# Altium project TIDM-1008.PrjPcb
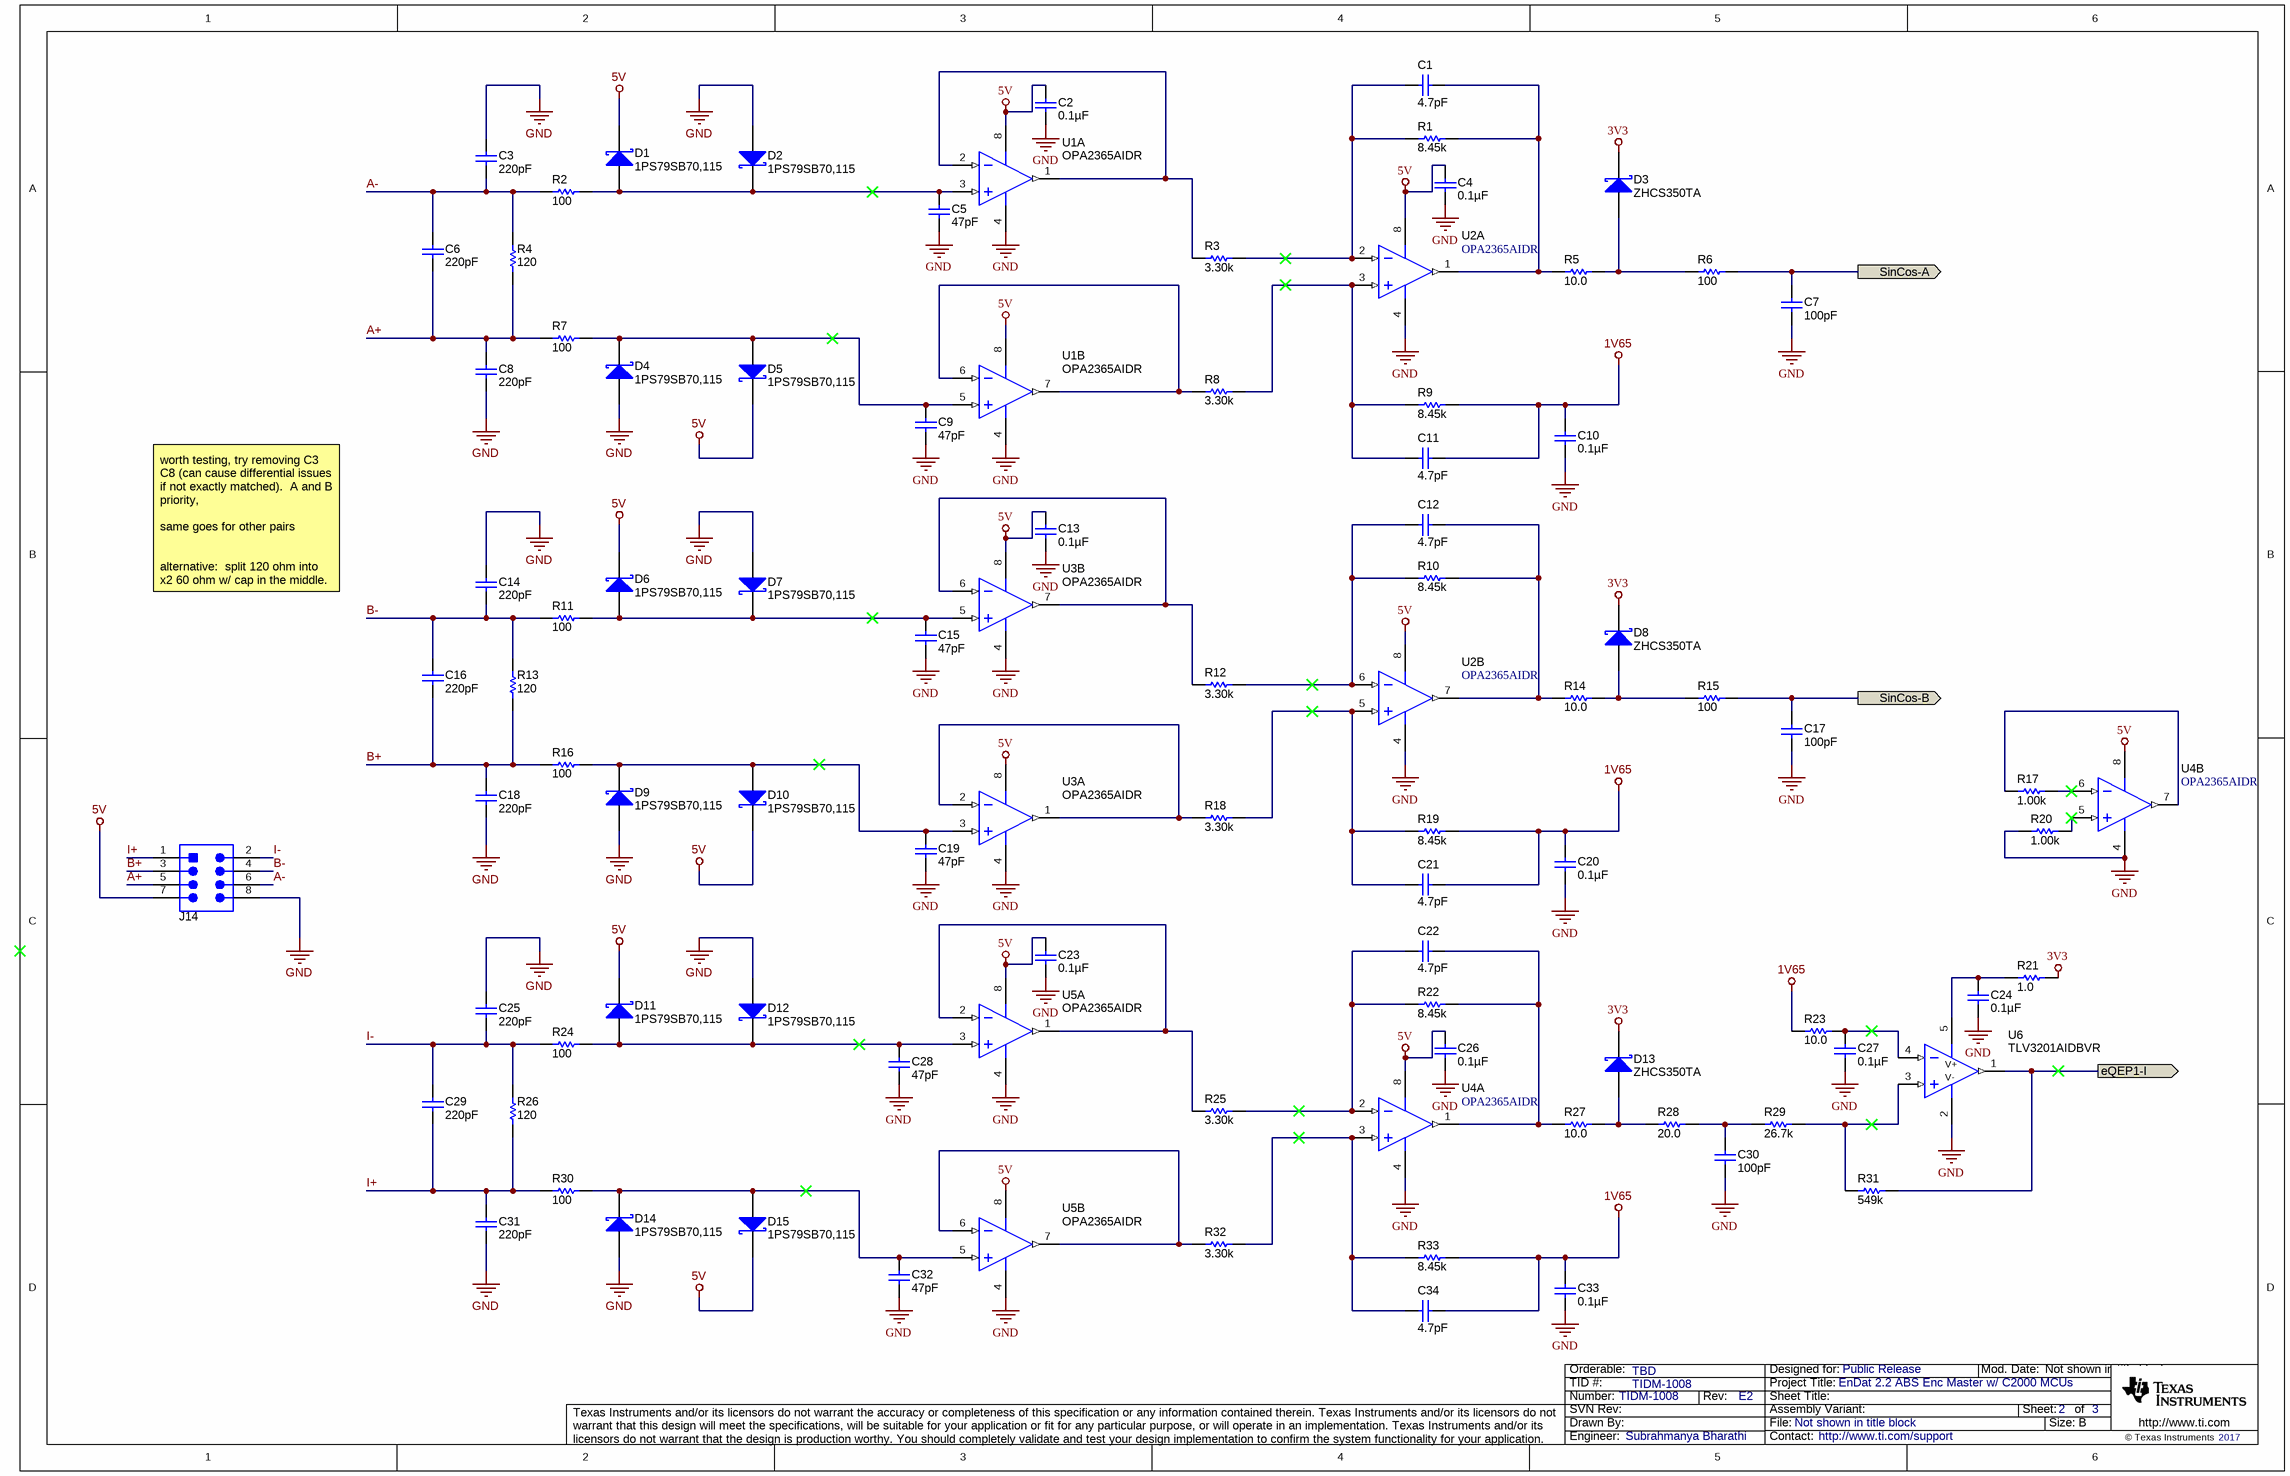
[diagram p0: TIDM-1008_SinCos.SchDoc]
CopyrightYear: 2017; EVM_Orderable: TBD; PCB_Layout: William Stevers; PCB_Rev: 002; PRJ_Customer: Public Release; PRJ_Engineer: Subrahmanya Bharathi; PRJ_Number: TIDM-1008; PRJ_Title: EnDat 2.2 ABS Enc Master w/ C2000 MCUs; SCH_Rev: E2; TechSupport: http://www.ti.com/support; TID: TIDM-1008
5 sheets, 197 parts. Net scope: flat (ports and power ports of the same name join across sheets).
Board file: TIDM-1008_PCB.~(15).PcbDoc
Sheets:
  TIDM-1008_SinCos.SchDoc
  TIDM-1008_AbsEnc.SchDoc
  TIDM-1008_Hardware.SchDoc
  TIDM-1008_Resolver.SchDoc
  TIDM-1008_PowerAndInterface.SchDoc

## Sheet TIDM-1008_SinCos.SchDoc
size 431 x 279 mm; Date: Not shown in title block; ApprovedBy: Not shown in title block; CheckedBy: Not shown in title block; Author: Not shown in title block; CompanyName: Not shown in title block; Engineer: Not shown in title block; Organization: Not shown in title block; Address1: Not shown in title block; Address2: Not shown in title block; Address3: Not shown in title block; Address4: Not shown in title block; DocumentNumber: 1; Revision: Use project parameter SCH_Rev; SheetNumber: 2; SheetTotal: 3; PageSetup: Record=PageOptions¦CenterHorizontal=True¦CenterVertical=True¦PrintScale=1.00¦XCorrection=1.00¦YCorrection=1.00¦PrintKind=0¦BorderSize=5000000¦LeftOffset=0¦BottomOffset=0¦Orientation=2¦PaperLength=1000¦PaperWidth=1000¦Scale=100¦PaperSource=15¦PrintQuality=600¦MediaType=1¦DitherType=10¦PaperKind=Letter¦PrintScaleMode=1

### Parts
C1  ValueDisplayed: 4.7pF  [0402]  (hidden comment: GRM1555C1H4R7WA01D)
C2  ValueDisplayed: 0.1µF  [0603]  (hidden comment: GRM188R71C104KA01D)
C3  ValueDisplayed: 220pF  [0603]  (hidden comment: GRM188R71H221KA01D)
C4  ValueDisplayed: 0.1µF  [0603]  (hidden comment: GRM188R71C104KA01D)
C5  ValueDisplayed: 47pF  [0402]  (hidden comment: GRM1555C1E470JA01D)
C6  ValueDisplayed: 220pF  [0603]  (hidden comment: GRM188R71H221KA01D)
C7  ValueDisplayed: 100pF  [0603]  (hidden comment: GRM1885C2A101JA01D)
C8  ValueDisplayed: 220pF  [0603]  (hidden comment: GRM188R71H221KA01D)
C9  ValueDisplayed: 47pF  [0402]  (hidden comment: GRM1555C1E470JA01D)
C10  ValueDisplayed: 0.1µF  [0402]  (hidden comment: GRM155R71C104KA88D)
C11  ValueDisplayed: 4.7pF  [0402]  (hidden comment: GRM1555C1H4R7WA01D)
C12  ValueDisplayed: 4.7pF  [0402]  (hidden comment: GRM1555C1H4R7WA01D)
C13  ValueDisplayed: 0.1µF  [0603]  (hidden comment: GRM188R71C104KA01D)
C14  ValueDisplayed: 220pF  [0603]  (hidden comment: GRM188R71H221KA01D)
C15  ValueDisplayed: 47pF  [0402]  (hidden comment: GRM1555C1E470JA01D)
C16  ValueDisplayed: 220pF  [0603]  (hidden comment: GRM188R71H221KA01D)
C17  ValueDisplayed: 100pF  [0603]  (hidden comment: GRM1885C2A101JA01D)
C18  ValueDisplayed: 220pF  [0603]  (hidden comment: GRM188R71H221KA01D)
C19  ValueDisplayed: 47pF  [0402]  (hidden comment: GRM1555C1E470JA01D)
C20  ValueDisplayed: 0.1µF  [0402]  (hidden comment: GRM155R71C104KA88D)
C21  ValueDisplayed: 4.7pF  [0402]  (hidden comment: GRM1555C1H4R7WA01D)
C22  ValueDisplayed: 4.7pF  [0402]  (hidden comment: GRM1555C1H4R7WA01D)
C23  ValueDisplayed: 0.1µF  [0603]  (hidden comment: GRM188R71C104KA01D)
C24  ValueDisplayed: 0.1µF  [0603]  (hidden comment: GRM188R71C104KA01D)
C25  ValueDisplayed: 220pF  [0603]  (hidden comment: GRM188R71H221KA01D)
C26  ValueDisplayed: 0.1µF  [0603]  (hidden comment: GRM188R71C104KA01D)
C27  ValueDisplayed: 0.1µF  [0402]  (hidden comment: GRM155R71C104KA88D)
C28  ValueDisplayed: 47pF  [0402]  (hidden comment: GRM1555C1E470JA01D)
C29  ValueDisplayed: 220pF  [0603]  (hidden comment: GRM188R71H221KA01D)
C30  ValueDisplayed: 100pF  [0603]  (hidden comment: GRM1885C2A101JA01D)
C31  ValueDisplayed: 220pF  [0603]  (hidden comment: GRM188R71H221KA01D)
C32  ValueDisplayed: 47pF  [0402]  (hidden comment: GRM1555C1E470JA01D)
C33  ValueDisplayed: 0.1µF  [0402]  (hidden comment: GRM155R71C104KA88D)
C34  ValueDisplayed: 4.7pF  [0402]  (hidden comment: GRM1555C1H4R7WA01D)
D1  1PS79SB70,115  [SOD-523]
D2  1PS79SB70,115  [SOD-523]
D3  ZHCS350TA  [SOD-523]
D4  1PS79SB70,115  [SOD-523]
D5  1PS79SB70,115  [SOD-523]
D6  1PS79SB70,115  [SOD-523]
D7  1PS79SB70,115  [SOD-523]
D8  ZHCS350TA  [SOD-523]
D9  1PS79SB70,115  [SOD-523]
D10  1PS79SB70,115  [SOD-523]
D11  1PS79SB70,115  [SOD-523]
D12  1PS79SB70,115  [SOD-523]
D13  ZHCS350TA  [SOD-523]
D14  1PS79SB70,115  [SOD-523]
D15  1PS79SB70,115  [SOD-523]
J14  70246-0801  [Molex_70246-0801]  (value not drawn)
R1  ValueDisplayed: 8.45k  [0402]  (hidden comment: ERA-2AEB8451X)
R2  ValueDisplayed: 100  [0402]  (hidden comment: CRCW0402100RJNED)
R3  ValueDisplayed: 3.30k  [0402]  (hidden comment: ERJ-2RKF3301X)
R4  ValueDisplayed: 120  [0603]  (hidden comment: CRCW0603120RJNEA)
R5  ValueDisplayed: 10.0  [0402]  (hidden comment: CRCW040210R0FKED)
R6  ValueDisplayed: 100  [0402]  (hidden comment: CRCW0402100RJNED)
R7  ValueDisplayed: 100  [0402]  (hidden comment: CRCW0402100RJNED)
R8  ValueDisplayed: 3.30k  [0402]  (hidden comment: ERJ-2RKF3301X)
R9  ValueDisplayed: 8.45k  [0402]  (hidden comment: ERA-2AEB8451X)
R10  ValueDisplayed: 8.45k  [0402]  (hidden comment: ERA-2AEB8451X)
R11  ValueDisplayed: 100  [0402]  (hidden comment: CRCW0402100RJNED)
R12  ValueDisplayed: 3.30k  [0402]  (hidden comment: ERJ-2RKF3301X)
R13  ValueDisplayed: 120  [0603]  (hidden comment: CRCW0603120RJNEA)
R14  ValueDisplayed: 10.0  [0402]  (hidden comment: CRCW040210R0FKED)
R15  ValueDisplayed: 100  [0402]  (hidden comment: CRCW0402100RJNED)
R16  ValueDisplayed: 100  [0402]  (hidden comment: CRCW0402100RJNED)
R17  ValueDisplayed: 1.00k  [0402]  (hidden comment: CRCW04021K00FKED)
R18  ValueDisplayed: 3.30k  [0402]  (hidden comment: ERJ-2RKF3301X)
R19  ValueDisplayed: 8.45k  [0402]  (hidden comment: ERA-2AEB8451X)
R20  ValueDisplayed: 1.00k  [0402]  (hidden comment: CRCW04021K00FKED)
R21  ValueDisplayed: 1.0  [0402]  (hidden comment: CRCW04021R00JNED)
R22  ValueDisplayed: 8.45k  [0402]  (hidden comment: ERA-2AEB8451X)
R23  ValueDisplayed: 10.0  [0402]  (hidden comment: CRCW040210R0FKED)
R24  ValueDisplayed: 100  [0402]  (hidden comment: CRCW0402100RJNED)
R25  ValueDisplayed: 3.30k  [0402]  (hidden comment: ERJ-2RKF3301X)
R26  ValueDisplayed: 120  [0603]  (hidden comment: CRCW0603120RJNEA)
R27  ValueDisplayed: 10.0  [0402]  (hidden comment: CRCW040210R0FKED)
R28  ValueDisplayed: 20.0  [0402]  (hidden comment: CRCW040220R0FKED)
R29  ValueDisplayed: 26.7k  [0402]  (hidden comment: CRCW040226K7FKED)
R30  ValueDisplayed: 100  [0402]  (hidden comment: CRCW0402100RJNED)
R31  ValueDisplayed: 549k  [0402]  (hidden comment: CRCW0402549KFKED)
R32  ValueDisplayed: 3.30k  [0402]  (hidden comment: ERJ-2RKF3301X)
R33  ValueDisplayed: 8.45k  [0402]  (hidden comment: ERA-2AEB8451X)
U1  OPA2365AIDR  [D0008A_N]  (parts A,B of 2)
U2  OPA2365AIDR  [D0008A_N]  (parts A,B of 2)
U3  OPA2365AIDR  [D0008A_N]  (parts A,B of 2)
U4  OPA2365AIDR  [D0008A_N]  (parts A,B of 2)
U5  OPA2365AIDR  [D0008A_N]  (parts A,B of 2)
U6  TLV3201AIDBVR  [DBV0005A_N]

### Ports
eQEP1-I (out), SinCos-A, SinCos-B (out)

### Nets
1V65: C10.1 C11.1 C20.1 C21.1 C33.1 C34.1 R9.2 R19.2 R23.1 R33.2
3V3: D3.1(K) D8.1(K) D13.1(K) R21.2
5V: C2.2 C4.2 C13.2 C23.2 C26.2 D1.1(K) D5.1(K) D6.1(K) D10.1(K) D11.1(K) D15.1(K) J14.7 U1.8(V+) U2.8(V+) U3.8(V+) U4.8(V+) U5.8(V+)
GND: C2.1 C3.1 C4.1 C5.2 C7.2 C8.2 C9.2 C10.2 C13.1 C14.1 C15.2 C17.2 C18.2 C19.2 C20.2 C23.1 C24.1 C25.1 C26.1 C27.2 C28.2 C30.2 C31.2 C32.2 C33.2 D2.2(A) D4.2(A) D7.2(A) D9.2(A) D12.2(A) D14.2(A) J14.8 R20.1 U1.4(V-) U2.4(V-) U3.4(V-) U4.4(V-) U5.4(V-) U6.2(V-)
A+: C6.2 C8.1 J14.5 R4.1 R7.1
A-: C3.2 C6.1 J14.6 R2.1 R4.2
B+: C16.2 C18.1 J14.3 R13.1 R16.1
B-: C14.2 C16.1 J14.4 R11.1 R13.2
eQEP1-I: R31.2 U6.1(OUT) ; port eQEP1-I
I+: C29.2 C31.1 J14.1 R26.1 R30.1
I-: C25.2 C29.1 J14.2 R24.1 R26.2
SinCos-A: C7.1 R6.2 ; port SinCos-A
SinCos-B: C17.1 R15.2 ; port SinCos-B
NetC1_1: C1.1 R1.2 R5.1 U2.1(VOUT_A)
NetC1_2: C1.2 R1.1 R3.2 U2.2(IN_A-)
NetC5_1: C5.1 D1.2(A) D2.1(K) R2.2 U1.3(IN_A+)
NetC9_1: C9.1 D4.1(K) D5.2(A) R7.2 U1.5(IN_B+)
NetC11_2: C11.2 R8.2 R9.1 U2.3(IN_A+)
NetC12_1: C12.1 R10.2 R14.1 U2.7(VOUT_B)
NetC12_2: C12.2 R10.1 R12.2 U2.6(IN_B-)
NetC15_1: C15.1 D6.2(A) D7.1(K) R11.2 U3.5(IN_B+)
NetC19_1: C19.1 D9.1(K) D10.2(A) R16.2 U3.3(IN_A+)
NetC21_2: C21.2 R18.2 R19.1 U2.5(IN_B+)
NetC22_1: C22.1 R22.2 R27.1 U4.1(VOUT_A)
NetC22_2: C22.2 R22.1 R25.2 U4.2(IN_A-)
NetC24_2: C24.2 R21.1 U6.5(V+)
NetC27_1: C27.1 R23.2 U6.4(IN-)
NetC28_1: C28.1 D11.2(A) D12.1(K) R24.2 U5.3(IN_A+)
NetC30_1: C30.1 R28.2 R29.1
NetC32_1: C32.1 D14.1(K) D15.2(A) R30.2 U5.5(IN_B+)
NetC34_2: C34.2 R32.2 R33.1 U4.3(IN_A+)
NetD3_2: D3.2(A) R5.2 R6.1
NetD8_2: D8.2(A) R14.2 R15.1
NetD13_2: D13.2(A) R27.2 R28.1
NetR3_1: R3.1 U1.1(VOUT_A) U1.2(IN_A-)
NetR8_1: R8.1 U1.6(IN_B-) U1.7(VOUT_B)
NetR12_1: R12.1 U3.6(IN_B-) U3.7(VOUT_B)
NetR17_1: R17.1 U4.7(VOUT_B)
NetR17_2: R17.2 U4.6(IN_B-)
NetR18_1: R18.1 U3.1(VOUT_A) U3.2(IN_A-)
NetR20_2: R20.2 U4.5(IN_B+)
NetR25_1: R25.1 U5.1(VOUT_A) U5.2(IN_A-)
NetR29_2: R29.2 R31.1 U6.3(IN+)
NetR32_1: R32.1 U5.6(IN_B-) U5.7(VOUT_B)

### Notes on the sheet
- worth testing, try removing C3 C8 (can cause differential issues if not exactly matched).  A and B priority,
  same goes for other pairs
  alternative:  split 120 ohm into x2 60 ohm w/ cap in the middle.  easier to match resistors.

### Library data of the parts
C1 C11 C12 C21 C22 C34 = GRM1555C1H4R7WA01D: CAP, CERM, 4.7 pF, 50 V, +/- 1%, C0G/NP0, 0402; Manufacturer: MuRata; Polarized: N; CompType: Capacitor; Value: 4.7pF; U/M: EA; Cap_F: 0.0000000000047; Tolerance_%: 1; Value1: Unknown; VDC_V: 50; Value2: 50V; TaMin_C: -55; TaMax_C: 125
C2 C4 C13 C23 C24 C26 = GRM188R71C104KA01D: CAP, CERM, 0.1 µF, 16 V, +/- 10%, X7R, 0603; Manufacturer: MuRata; Polarized: N; CompType: Capacitor; Value: 0.1uF; U/M: EA; Cap_F: 0.0000001; Tolerance_%: 10; Value1: Unknown; VDC_V: 16; Value2: 16V; TaMin_C: -55; TaMax_C: 125
C3 C6 C8 C14 C16 C18 C25 C29 C31 = GRM188R71H221KA01D: CAP, CERM, 220 pF, 50 V, +/- 10%, X7R, 0603; Manufacturer: MuRata; Polarized: N; CompType: Capacitor; Value: 220pF; U/M: EA; Cap_F: 0.00000000022; Tolerance_%: 10; Value1: Unknown; VDC_V: 50; Value2: 50V; TaMin_C: -55; TaMax_C: 125; SizeArea_mm2: 1.28; SizeAreaWB_mm2: 4.68; SizeX_mm: 1.6; SizeY_mm: 0.8; SizeZ_mm: 1; AEC Category: Q200
C5 C9 C15 C19 C28 C32 = GRM1555C1E470JA01D: CAP, CERM, 47 pF, 25 V, +/- 5%, C0G/NP0, 0402; Manufacturer: MuRata; Polarized: N; CompType: Capacitor; Value: 47pF; U/M: EA; Cap_F: 0.000000000047; Tolerance_%: 5; Value1: Unknown; VDC_V: 25; Value2: 25V; TaMin_C: -55; TaMax_C: 125
C7 C17 C30 = GRM1885C2A101JA01D: CAP, CERM, 100 pF, 100 V,+/- 5%, C0G/NP0, 0603; Manufacturer: MuRata; Polarized: N; CompType: Capacitor; Value: 100pF; U/M: EA; Cap_F: 0.0000000001; Tolerance_%: 5; Value1: Unknown; VDC_V: 100; Value2: 100V; TaMin_C: -55; TaMax_C: 125; SizeArea_mm2: 1.28; SizeAreaWB_mm2: 4.68; SizeX_mm: 1.6; SizeY_mm: 0.8; SizeZ_mm: 1; AEC Category: Q200; Green_Lifecycle: Active; Green_REACh: Passed
C10 C20 C27 C33 = GRM155R71C104KA88D: CAP, CERM, 0.1 µF, 16 V, +/- 10%, X7R, 0402; Manufacturer: MuRata; Polarized: N; CompType: Capacitor; Value: 0.1uF; U/M: EA; Cap_F: 0.0000001; Tolerance_%: 10; Value1: Unknown; VDC_V: 16; Value2: 16V; TaMin_C: -55; TaMax_C: 125
D1 D2 D4-D7 D9-D12 D14 D15 = 1PS79SB70,115: Diode, Schottky, 70 V, 0.07 A, SOD-523; Manufacturer: NXP Semiconductor; U/M: EA; Vf_V: 0.41; Value: 70V; Value1: 0.07A; Value2: 0.41V; Io_A: 0.07; Vr_V: 70; TJmax_C: 150; SizeAreaWB_mm2: 5.13; SizeArea_mm2: 1.53; SizeX_mm: 1.7; SizeY_mm: 0.9; SizeZ_mm: 0.65; AEC Category: Q101
D3 D8 D13 = ZHCS350TA: Diode, Schottky, 40 V, 0.35 A, SOD-523; Manufacturer: Diodes Inc.; U/M: EA; Vf_V: 0.65; Value: 40V; Value1: 0.35A; Value2: 0.65V; Io_A: 0.35; Vr_V: 40
J14 = 70246-0801: Header(shrouded), 2.54mm, 4x2, Gold, TH; Manufacturer: Molex; SymbolCreator: a0411947; Pitch_mm: 2.54; Gender: Male; Shrouded: Y; Row_Count: 2; Current_A: 2.5; Voltage_V: 250
R1 R9 R10 R19 R22 R33 = ERA-2AEB8451X: RES, 8.45 k, 0.1%, 0.063 W, 0402; Manufacturer: Panasonic; CompType: Resistor; Value: 8.45k; Res_ohm: 8450; Value_Code: 8k45; Tolerance_%: 0.1; Power_W: 0.063; Value2: 0.063W; VDC_V: 50; TempCo: 25 ppm/C; EIA_Code: E192; U/M: EA
R2 R7 R11 R16 R24 R30 = CRCW0402100RJNED: RES, 100, 5%, 0.063 W, 0402; Manufacturer: Vishay-Dale; CompType: Resistor; Value: 100; Value_Code: 100R; Tolerance_%: 5; Power_W: 0.063; Value2: 0.063W; VDC_V: 50; TempCo: 200 ppm/C; SizeArea_mm2: 0.5; SizeX_mm: 1; SizeZ_mm: 0.6; EIA_Code: E24; U/M: EA; AEC Category: Q200
R3 R8 R12 R18 R25 R32 = ERJ-2RKF3301X: RES, 3.30 k, 1%, 0.1 W, AEC-Q200 Grade 0, 0402; Manufacturer: Panasonic; CompType: Resistor; Value: 3.30k; Res_ohm: 3300; Value_Code: 3k30; Tolerance_%: 1; Power_W: 0.1; Value2: 0.1W; VDC_V: 50; TempCo: 100 ppm/C; U/M: EA; SizeArea_mm2: 0.5; SizeZ_mm: 0.6; AEC Category: Q200; AEC Qualified: Y; AEC Grade: 0
R4 R13 R26 = CRCW0603120RJNEA: RES, 120, 5%, 0.1 W, 0603; Manufacturer: Vishay-Dale; CompType: Resistor; Value: 120; Value_Code: 120R; Tolerance_%: 5; Power_W: 0.1; Value2: 0.1W; VDC_V: 75; TempCo: 200 ppm/C; SizeArea_mm2: 1.28; SizeX_mm: 1.6; SizeY_mm: 0.8; SizeZ_mm: 1; EIA_Code: E24; U/M: EA; AEC Category: Q200
R5 R14 R23 R27 = CRCW040210R0FKED: RES, 10.0, 1%, 0.063 W, 0402; Manufacturer: Vishay-Dale; CompType: Resistor; Value: 10.0; Res_ohm: 10; Value_Code: 10R0; Tolerance_%: 1; Power_W: 0.063; Value2: 0.063W; VDC_V: 50; TempCo: 100 ppm/C; EIA_Code: E96; U/M: EA
R6 R15 = CRCW0402100RJNED: RES, 100, 5%, 0.063 W, 0402; Manufacturer: Vishay-Dale; CompType: Resistor; Value: 100; Value_Code: 100R; Tolerance_%: 5; Power_W: 0.063; Value2: 0.063W; VDC_V: 50; TempCo: 200 ppm/C; EIA_Code: E24; U/M: EA
R17 R20 = CRCW04021K00FKED: RES, 1.00 k, 1%, 0.063 W, 0402; Manufacturer: Vishay-Dale; CompType: Resistor; Value: 1.00k; Res_ohm: 1000; Value_Code: 1k00; Tolerance_%: 1; Power_W: 0.063; Value2: 0.063W; VDC_V: 50; TempCo: 100 ppm/C; EIA_Code: E96; U/M: EA
R21 = CRCW04021R00JNED: RES, 1.0, 5%, 0.063 W, 0402; Manufacturer: Vishay-Dale; CompType: Resistor; Value: 1.0; Res_ohm: 1; Value_Code: 1R00; Tolerance_%: 5; Power_W: 0.063; Value2: 0.063W; VDC_V: 50; TempCo: 200 ppm/C; EIA_Code: E24; U/M: EA
R28 = CRCW040220R0FKED: RES, 20.0, 1%, 0.063 W, 0402; Manufacturer: Vishay-Dale; CompType: Resistor; Value: 20.0; Res_ohm: 20; Value_Code: 20R0; Tolerance_%: 1; Power_W: 0.063; Value2: 0.063W; VDC_V: 50; TempCo: 100 ppm/C; EIA_Code: E96; U/M: EA
R29 = CRCW040226K7FKED: RES, 26.7 k, 1%, 0.063 W, 0402; Manufacturer: Vishay-Dale; CompType: Resistor; Value: 26.7k; Res_ohm: 26700; Value_Code: 26k7; Tolerance_%: 1; Power_W: 0.063; Value2: 0.063W; VDC_V: 50; TempCo: 100 ppm/C; EIA_Code: E96; U/M: EA
R31 = CRCW0402549KFKED: RES, 549 k, 1%, 0.063 W, 0402; Manufacturer: Vishay-Dale; CompType: Resistor; Value: 549k; Res_ohm: 549000; Tolerance_%: 1; Power_W: 0.063; Value2: 0.063W; VDC_V: 50; TempCo: 100 ppm/C; EIA_Code: E96; U/M: EA
U1 U3 U5 = OPA2365AIDR: 50 MHz, Low-Noise Single-Supply Rail-to-Rail Operational Amplifier, 2.2 to 5.5 V, -40 to 125 degC, 8-pin SOIC (D0008A), Green (RoHS & no Sb/Br); Manufacturer: Texas Instruments; Alternate Manufacturer: None; Alternate PartNumber: Equivalent; CMRR(Min)(dB): 100; IIB(Max)(pA): 10; Iq per channel(Max)(mA): 5; Number of Channels: 2; Offset Drift(Typ)(uV/C): 1; Slew Rate(Typ)(V/us): 25; Sub Family: High Speed Amplifier (>=50MHz), Low Input Bias Current Amp (<=10pA), Low Offset Voltage Amplifier (<=500uV), Low Supply Voltage Amplifier (<=2.7V); Total Supply Voltage(Max)(+5V is 5, +/-5V is 10): 5.5; Total Supply Voltage(Min)(+5V is 5, +/-5V is 10): 2.2; Vio (25C)(Max)(mV): 0.2
U2 U4 = OPA2365AIDR: 50 MHz, Low-Noise Single-Supply Rail-to-Rail Operational Amplifier, 2.2 to 5.5 V, -40 to 125 degC, 8-pin SOIC (D0008A), Green (RoHS & no Sb/Br); Manufacturer: Texas Instruments; Alternate Manufacturer: None; Alternate PartNumber: Equivalent; Iq per channel(Max)(mA): 5; Number of Channels: 2; Slew Rate(Typ)(V/us): 25; Sub Family: High Speed Amplifier (>=50MHz), Low Input Bias Current Amp (<=10pA), Low Offset Voltage Amplifier (<=500uV), Low Supply Voltage Amplifier (<=2.7V); CMRR(Min)(dB): 100; IIB(Max)(pA): 10; Offset Drift(Typ)(uV/C): 1; Total Supply Voltage(Max)(+5V is 5, +/-5V is 10): 5.5; Total Supply Voltage(Min)(+5V is 5, +/-5V is 10): 2.2; Vio (25C)(Max)(mV): 0.2
U6 = TLV3201AIDBVR: 40-ns, microPOWER, Push-Pull Output Comparators, DBV0005A; Alternate PartNumber: TLV3201AIDBVT; Manufacturer: Texas Instruments; SizeArea_mm2: 8.12; SizeAreaWB_mm2: 14.82; SizeX_mm: 2.8; SizeY_mm: 2.9; SizeZ_mm: 1.45; CompType: IC; U/M: EA

## Sheet TIDM-1008_AbsEnc.SchDoc
size 431 x 279 mm; Date: Not shown in title block; ApprovedBy: Not shown in title block; CheckedBy: Not shown in title block; Author: Not shown in title block; CompanyName: Not shown in title block; Engineer: Not shown in title block; Organization: Not shown in title block; Address1: Not shown in title block; Address2: Not shown in title block; Address3: Not shown in title block; Address4: Not shown in title block; DocumentNumber: 1; Revision: Use project parameter SCH_Rev; SheetNumber: 2; SheetTotal: 3; PageSetup: Record=PageOptions¦CenterHorizontal=True¦CenterVertical=True¦PrintScale=1.00¦XCorrection=1.00¦YCorrection=1.00¦PrintKind=0¦BorderSize=5000000¦LeftOffset=0¦BottomOffset=0¦Orientation=2¦PaperLength=1000¦PaperWidth=1000¦Scale=100¦PaperSource=15¦PrintQuality=600¦MediaType=1¦DitherType=10¦PaperKind=Letter¦PrintScaleMode=1
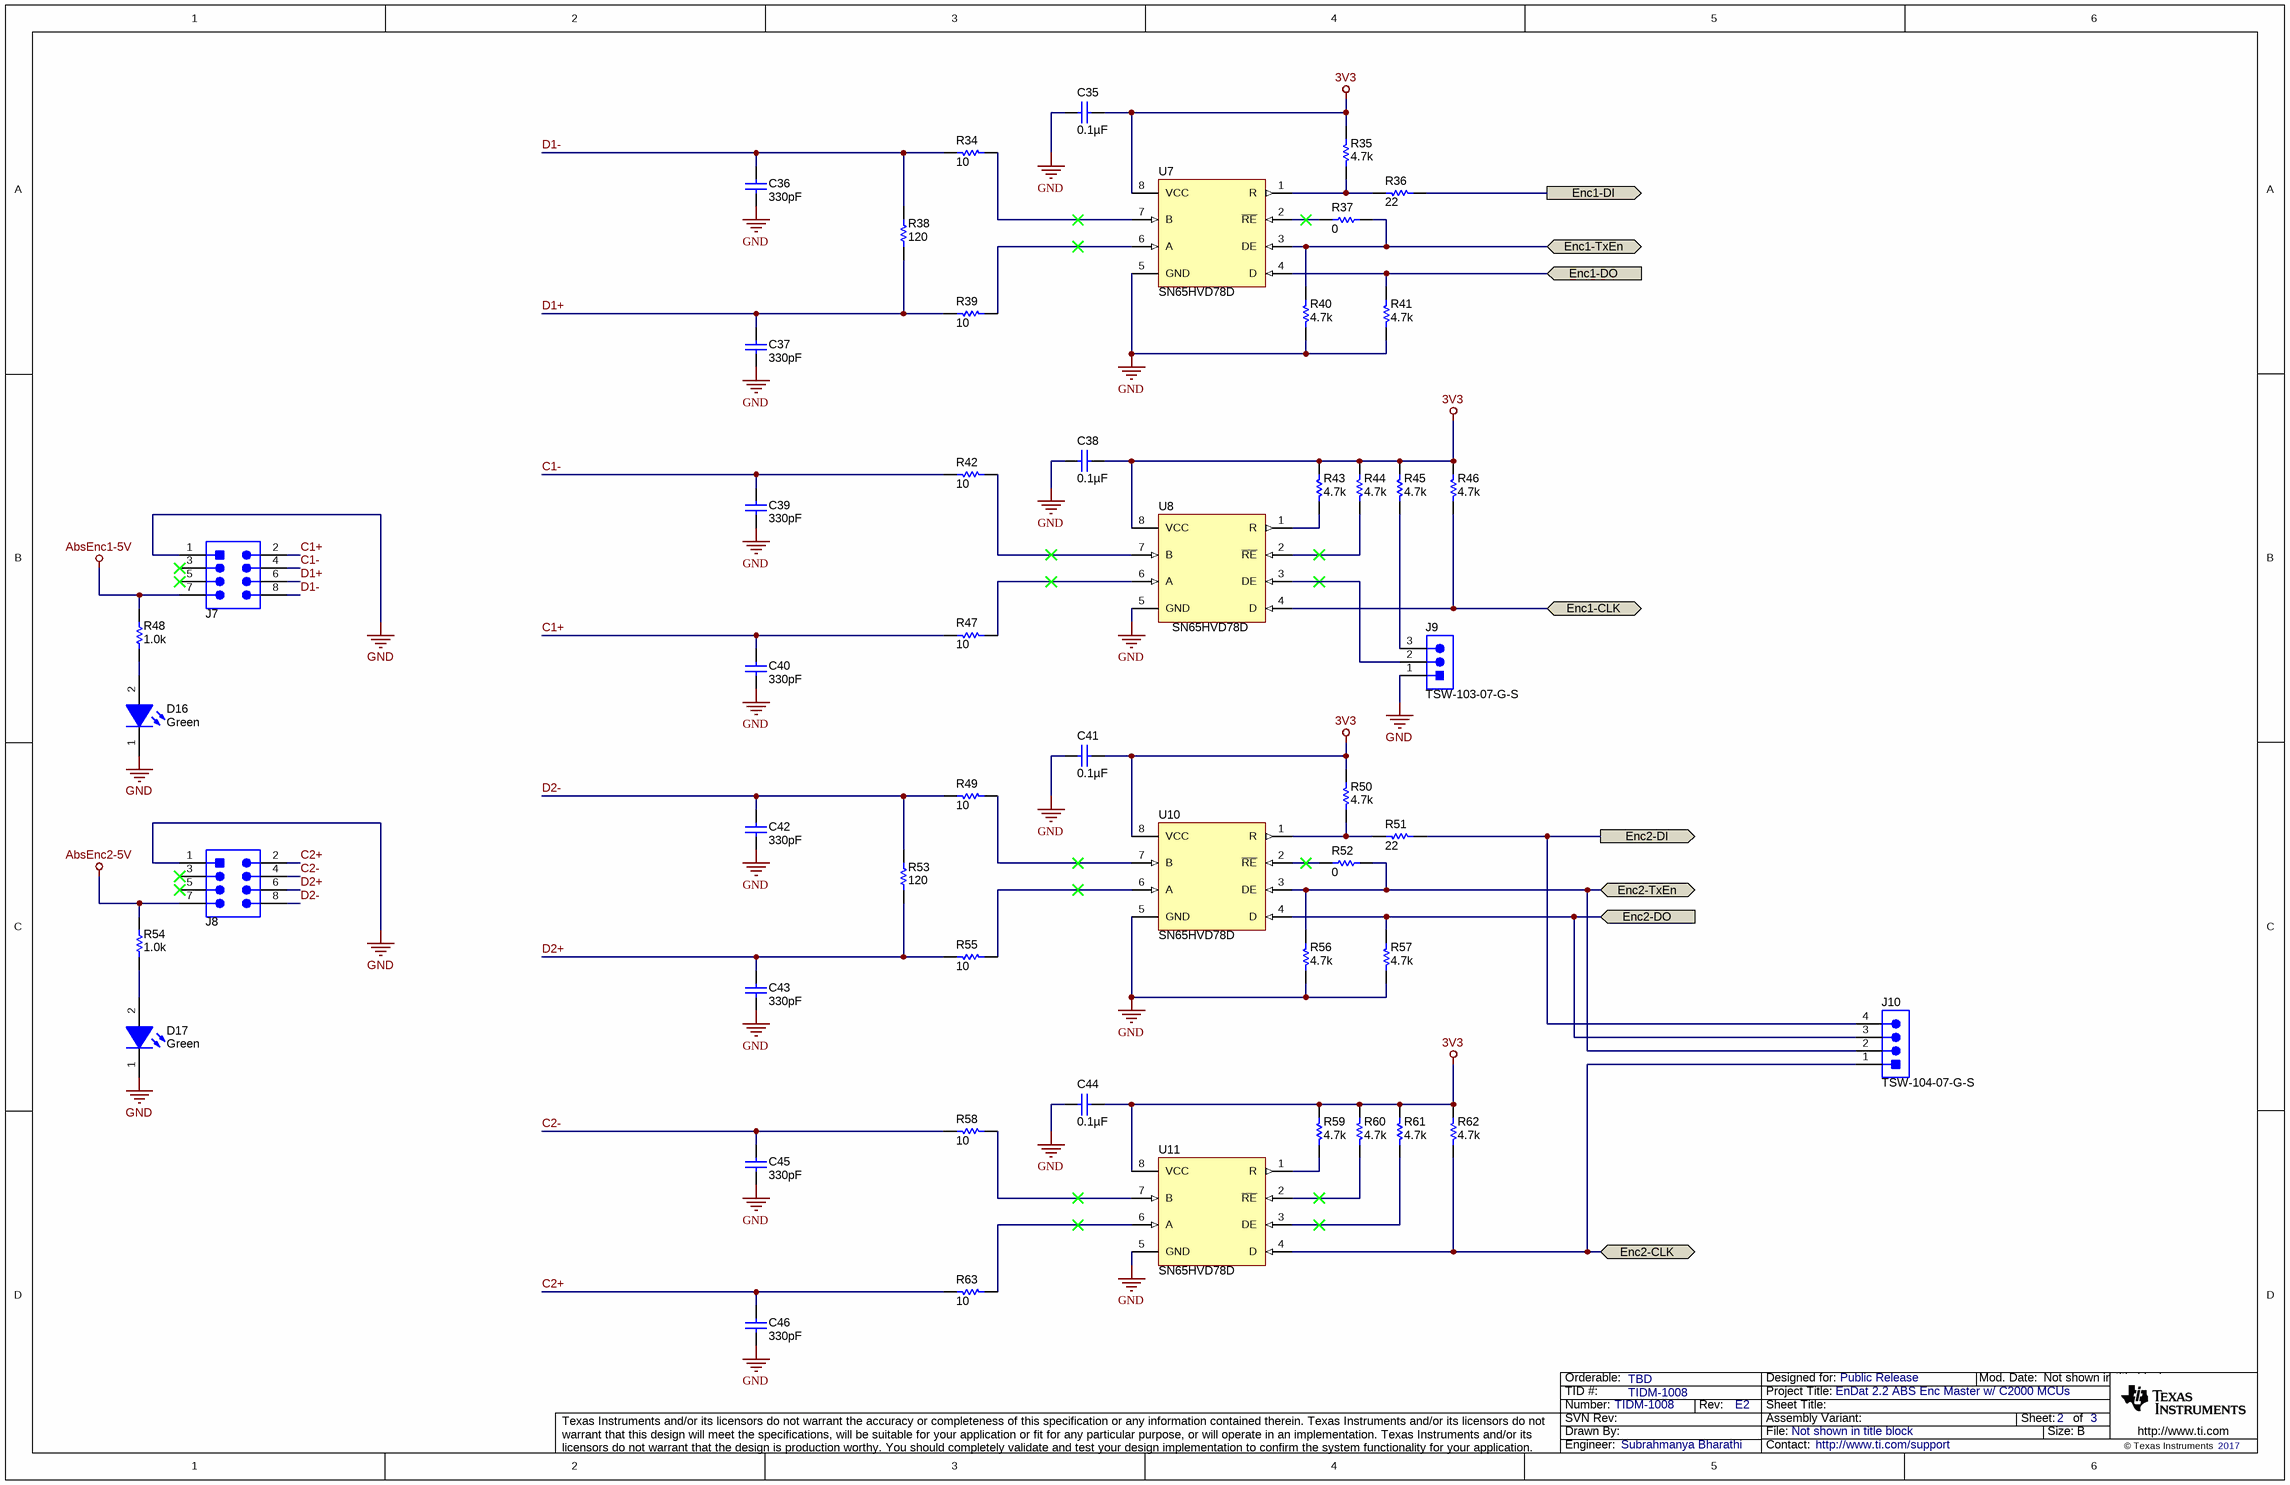
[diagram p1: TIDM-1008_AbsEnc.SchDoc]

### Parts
C35  ValueDisplayed: 0.1µF  [0603]  (hidden comment: 06033D104KAT2A)
C36  ValueDisplayed: 330pF  [0603]  (hidden comment: GRM188R71H331KA01D)
C37  ValueDisplayed: 330pF  [0603]  (hidden comment: GRM188R71H331KA01D)
C38  ValueDisplayed: 0.1µF  [0603]  (hidden comment: 06033D104KAT2A)
C39  ValueDisplayed: 330pF  [0603]  (hidden comment: GRM188R71H331KA01D)
C40  ValueDisplayed: 330pF  [0603]  (hidden comment: GRM188R71H331KA01D)
C41  ValueDisplayed: 0.1µF  [0603]  (hidden comment: 06033D104KAT2A)
C42  ValueDisplayed: 330pF  [0603]  (hidden comment: GRM188R71H331KA01D)
C43  ValueDisplayed: 330pF  [0603]  (hidden comment: GRM188R71H331KA01D)
C44  ValueDisplayed: 0.1µF  [0603]  (hidden comment: 06033D104KAT2A)
C45  ValueDisplayed: 330pF  [0603]  (hidden comment: GRM188R71H331KA01D)
C46  ValueDisplayed: 330pF  [0603]  (hidden comment: GRM188R71H331KA01D)
D16  value Green  [WL-SMCW_GREEN]  (hidden comment: 150060GS75000)
D17  value Green  [WL-SMCW_GREEN]  (hidden comment: 150060GS75000)
J7  70246-0801  [Molex_70246-0801]  (value not drawn)
J8  70246-0801  [Molex_70246-0801]  (value not drawn)
J9  TSW-103-07-G-S  [TSW-103-07-G-S]
J10  TSW-104-07-G-S  [TSW-104-07-G-S]
R34  value 10  [0603]  (hidden comment: CRCW060310R0JNEAHP)
R35  value 4.7k  [0603]  (hidden comment: CRCW06034K70JNEA)
R36  value 22  [0603]  (hidden comment: CRCW060322R0JNEA)
R37  ValueDisplayed: 0  [0603]  (hidden comment: CRCW06030000Z0EA)
R38  ValueDisplayed: 120  [0603]  (hidden comment: CRCW0603120RJNEA)
R39  value 10  [0603]  (hidden comment: CRCW060310R0JNEAHP)
R40  value 4.7k  [0603]  (hidden comment: CRCW06034K70JNEA)
R41  value 4.7k  [0603]  (hidden comment: CRCW06034K70JNEA)
R42  value 10  [0603]  (hidden comment: CRCW060310R0JNEAHP)
R43  value 4.7k  [0603]  (hidden comment: CRCW06034K70JNEA)
R44  value 4.7k  [0603]  (hidden comment: CRCW06034K70JNEA)
R45  value 4.7k  [0603]  (hidden comment: CRCW06034K70JNEA)
R46  value 4.7k  [0603]  (hidden comment: CRCW06034K70JNEA)
R47  value 10  [0603]  (hidden comment: CRCW060310R0JNEAHP)
R48  ValueDisplayed: 1.0k  [0402]  (hidden comment: CRCW04021K00JNED)
R49  value 10  [0603]  (hidden comment: CRCW060310R0JNEAHP)
R50  value 4.7k  [0603]  (hidden comment: CRCW06034K70JNEA)
R51  value 22  [0603]  (hidden comment: CRCW060322R0JNEA)
R52  ValueDisplayed: 0  [0603]  (hidden comment: CRCW06030000Z0EA)
R53  ValueDisplayed: 120  [0603]  (hidden comment: CRCW0603120RJNEA)
R54  ValueDisplayed: 1.0k  [0402]  (hidden comment: CRCW04021K00JNED)
R55  value 10  [0603]  (hidden comment: CRCW060310R0JNEAHP)
R56  value 4.7k  [0603]  (hidden comment: CRCW06034K70JNEA)
R57  value 4.7k  [0603]  (hidden comment: CRCW06034K70JNEA)
R58  value 10  [0603]  (hidden comment: CRCW060310R0JNEAHP)
R59  value 4.7k  [0603]  (hidden comment: CRCW06034K70JNEA)
R60  value 4.7k  [0603]  (hidden comment: CRCW06034K70JNEA)
R61  value 4.7k  [0603]  (hidden comment: CRCW06034K70JNEA)
R62  value 4.7k  [0603]  (hidden comment: CRCW06034K70JNEA)
R63  value 10  [0603]  (hidden comment: CRCW060310R0JNEAHP)
U7  SN65HVD78D  [D0008A_N]
U8  SN65HVD78D  [D0008A_N]
U10  SN65HVD78D  [D0008A_N]
U11  SN65HVD78D  [D0008A_N]

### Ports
Enc1-CLK (bidir), Enc1-DI (out), Enc1-DO (in), Enc1-TxEn (bidir), Enc2-CLK (bidir), Enc2-DI (out), Enc2-DO (in), Enc2-TxEn (bidir)

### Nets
3V3: C35.2 C38.2 C41.2 C44.2 R35.2 R43.2 R44.2 R45.2 R46.2 R50.2 R59.2 R60.2 R61.2 R62.2 U7.8(VCC) U8.8(VCC) U10.8(VCC) U11.8(VCC)
AbsEnc1-5V: J7.7 R48.2
AbsEnc2-5V: J8.7 R54.2
GND: C35.1 C36.1 C37.2 C38.1 C39.1 C40.2 C41.1 C42.1 C43.2 C44.1 C45.1 C46.2 D16.1(K) D17.1(K) J7.1 J8.1 J9.1 R40.2 R41.1 R56.2 R57.1 U7.5(GND) U8.5(GND) U10.5(GND) U11.5(GND)
C1+: C40.1 J7.2 R47.2
C1-: C39.2 J7.4 R42.2
C2+: C46.1 J8.2 R63.2
C2-: C45.2 J8.4 R58.2
D1+: C37.1 J7.6 R38.1 R39.2
D1-: C36.2 J7.8 R34.2 R38.2
D2+: C43.1 J8.6 R53.1 R55.2
D2-: C42.2 J8.8 R49.2 R53.2
Enc1-CLK: R46.1 U8.4(D) ; port Enc1-CLK
Enc1-TxEn: R37.2 R40.1 U7.3(DE) ; port Enc1-TxEn
Enc2-CLK: J10.1 R62.1 U11.4(D) ; port Enc2-CLK
Enc2-TxEn: J10.2 R52.2 R56.1 U10.3(DE) ; port Enc2-TxEn
SPI-1-SIMO: R36.1 ; port Enc1-DI
SPI-1-SOMI: R41.2 U7.4(D) ; port Enc1-DO
SPI-2-SIMO: J10.4 R51.1 ; port Enc2-DI
SPI-2-SOMI: J10.3 R57.2 U10.4(D) ; port Enc2-DO
NetD16_2: D16.2(A) R48.1
NetD17_2: D17.2(A) R54.1
NetJ9_2: J9.2 U8.3(DE)
NetJ9_3: J9.3 R45.1
NetR34_1: R34.1 U7.7(B)
NetR35_1: R35.1 R36.2 U7.1(R)
NetR37_1: R37.1 U7.2(~{RE})
NetR39_1: R39.1 U7.6(A)
NetR42_1: R42.1 U8.7(B)
NetR43_1: R43.1 U8.1(R)
NetR44_1: R44.1 U8.2(~{RE})
NetR47_1: R47.1 U8.6(A)
NetR49_1: R49.1 U10.7(B)
NetR50_1: R50.1 R51.2 U10.1(R)
NetR52_1: R52.1 U10.2(~{RE})
NetR55_1: R55.1 U10.6(A)
NetR58_1: R58.1 U11.7(B)
NetR59_1: R59.1 U11.1(R)
NetR60_1: R60.1 U11.2(~{RE})
NetR61_1: R61.1 U11.3(DE)
NetR63_1: R63.1 U11.6(A)

Not connected (* = marked no-connect by the designer): J7 3* 5*; J8 3* 5*

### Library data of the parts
C35 C38 C41 C44 = 06033D104KAT2A: CAP, CERM, 0.1uF, 25V, +/-10%, X5R, 0603; Manufacturer: AVX; Polarized: N; CompType: Capacitor; U/M: EA; Cap_F: 0.0000001; Tolerance_%: 10; ESR_Ohm: 0.048; Value1: 0.048 ohm; VDC_V: 25; IRMS_A: 0.53; TaMin_C: -55; TaMax_C: 85
C36 C37 C39 C40 C42 C43 C45 C46 = GRM188R71H331KA01D: CAP, CERM, 330pF, 50V, +/-10%, X7R, 0603; Manufacturer: MuRata; Polarized: N; CompType: Capacitor; U/M: EA; Cap_F: 0.00000000033; Tolerance_%: 10; Value1: Unknown; VDC_V: 50; TaMin_C: -55; TaMax_C: 125
D16 D17 = 150060GS75000: LED, Green, SMD; Manufacturer: Wurth Elektronik; Type: InGaN; Vf_V: 3.2; Value2: 3.2V; Io_A: 0.02; Tjmax_C: 85; Value1: W; Angle: 140; U/M: EA; Green_Lifecycle: Active; Green_REACh: Passed
J7 J8 = 70246-0801: as J14 on sheet TIDM-1008_SinCos
J9 = TSW-103-07-G-S: Header, 100mil, 3x1, Gold, TH; Manufacturer: Samtec; SymbolCreator: a0799628; Pitch_mm: 2.54; Gender: Male; Shrouded: N; Row_Count: 1; Current_A: 6.3; Voltage_V: 550; Cert_CSA: Y
J10 = TSW-104-07-G-S: Header, 100mil, 4x1, Gold, TH; Manufacturer: Samtec; SymbolCreator: a0412235; Pitch_mm: 2.54; Gender: Male; Shrouded: N; Row_Count: 1; Current_A: 6.3; Voltage_V: 550; Cert_CSA: Y
R34 R39 R42 R47 R49 R55 R58 R63 = CRCW060310R0JNEAHP: RES, 10 ohm, 5%, 0.25W, 0603; Manufacturer: Vishay-Dale; CompType: Resistor; Value_Code: 10R0; Tolerance_%: 5; Power_W: 0.25; VDC_V: 75; TempCo: 200 ppm/C; EIA_Code: E24; U/M: EA
R35 R40 R41 R43-R46 R50 R56 R57 R59-R62 = CRCW06034K70JNEA: RES, 4.7k ohm, 5%, 0.1W, 0603; Manufacturer: Vishay-Dale; CompType: Resistor; Res_ohm: 4700; Value_Code: 4k70; Tolerance_%: 5; Power_W: 0.1; VDC_V: 75; TempCo: 200 ppm/C; EIA_Code: E24; U/M: EA
R36 R51 = CRCW060322R0JNEA: RES, 22 ohm, 5%, 0.1W, 0603; Manufacturer: Vishay-Dale; CompType: Resistor; Value_Code: 22R0; Tolerance_%: 5; Power_W: 0.1; VDC_V: 75; TempCo: 200 ppm/C; EIA_Code: E24; U/M: EA
R37 R52 = CRCW06030000Z0EA: RES, 0, 5%, 0.1 W, 0603; Manufacturer: Vishay-Dale; CompType: Resistor; Value: 0; Value_Code: 0000; Tolerance_%: 5; Power_W: 0.1; Value2: 0.1W; VDC_V: 75; TempCo: 200 ppm/C; SizeArea_mm2: 1.28; SizeX_mm: 1.6; SizeY_mm: 0.8; SizeZ_mm: 1; EIA_Code: E24; U/M: EA; AEC Category: Q200
R38 R53 = CRCW0603120RJNEA: as R4 on sheet TIDM-1008_SinCos
R48 R54 = CRCW04021K00JNED: RES, 1.0 k, 5%, 0.063 W, 0402; Manufacturer: Vishay-Dale; CompType: Resistor; Value: 1.0k; Res_ohm: 1000; Value_Code: 1k00; Tolerance_%: 5; Power_W: 0.063; Value2: 0.063W; VDC_V: 50; TempCo: 200 ppm/C; SizeArea_mm2: 0.5; SizeX_mm: 1; SizeZ_mm: 0.6; EIA_Code: E24; U/M: EA; AEC Category: Q200
U7 U8 U10 U11 = SN65HVD78D: 3.3V-Supply RS-485 with IEC ESD Protection, D0008A; Alternate Manufacturer: None; Manufacturer: Texas Instruments; SymbolCreator: a0411947; CompType: IC; U/M: EA

## Sheet TIDM-1008_Hardware.SchDoc
size 431 x 279 mm; Date: Not shown in title block; ApprovedBy: Not shown in title block; CheckedBy: Not shown in title block; Author: Not shown in title block; CompanyName: Not shown in title block; Engineer: Not shown in title block; Organization: Not shown in title block; Address1: Not shown in title block; Address2: Not shown in title block; Address3: Not shown in title block; Address4: Not shown in title block; DocumentNumber: 1; Revision: Use project parameter SCH_Rev; SheetNumber: 3; SheetTotal: 3; PageSetup: Record=PageOptions¦CenterHorizontal=True¦CenterVertical=True¦PrintScale=1.00¦XCorrection=1.00¦YCorrection=1.00¦PrintKind=0¦BorderSize=5000000¦LeftOffset=0¦BottomOffset=0¦Orientation=2¦PaperLength=1000¦PaperWidth=1000¦Scale=100¦PaperSource=15¦PrintQuality=600¦MediaType=1¦DitherType=10¦PaperKind=Letter¦PrintScaleMode=1
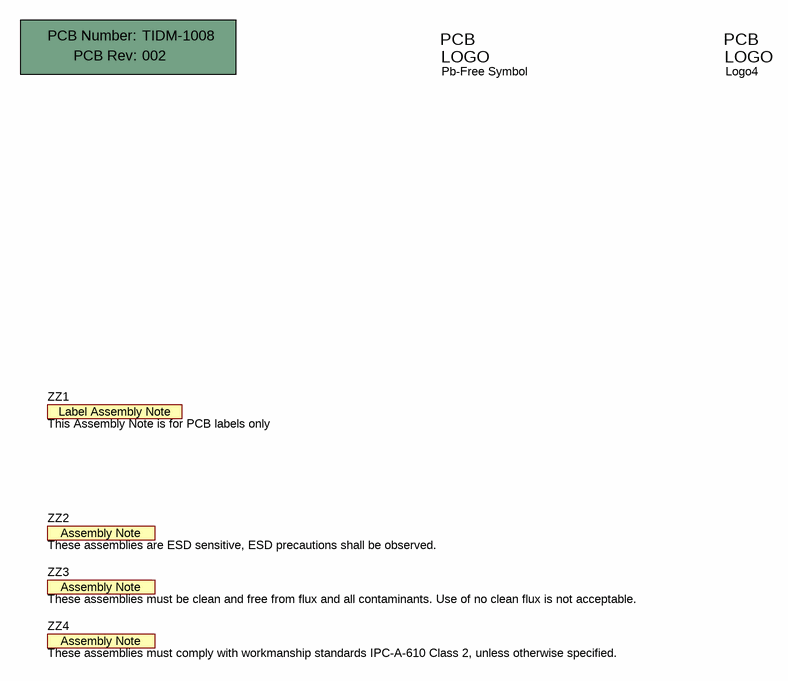
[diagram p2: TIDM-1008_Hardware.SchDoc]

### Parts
!PCB1  Printed Circuit Board  (value not drawn)  (mechanical)
Logo2  Pb-Free Symbol  [Pb-Free_Overlay_Small]  (no BOM)
Logo4  FCC disclaimer  [FCC_disclaimer]  (value not drawn)  (no BOM)
ZZ1  This Assembly Note is for PCB labels only  [AssemblyNoteLabel]  (no BOM)
ZZ2  These assemblies are ESD sensitive, ESD precautions shall be observed.  [AssemblyNote]  (no BOM)
ZZ3  These assemblies must be clean and free from flux and all contaminants. Use of no clean flux is not acceptable.  [AssemblyNote]  (no BOM)
ZZ4  These assemblies must comply with workmanship standards IPC-A-610 Class 2, unless otherwise specified.  [AssemblyNote]  (no BOM)

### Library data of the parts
!PCB1 = PCB: Manufacturer: Any; SymbolCreator: a0412235
Logo2 = Pb-Free: SymbolCreator: a0412235
Logo4 = FCC_disclaimer: SymbolCreator: a0412235
ZZ1 = AssemblyNoteLabel: SymbolCreator: a0412235
ZZ2-ZZ4 = AssemblyNote: SymbolCreator: codlsc

## Sheet TIDM-1008_Resolver.SchDoc
size 431 x 279 mm; Date: Not shown in title block; ApprovedBy: Not shown in title block; CheckedBy: Not shown in title block; Author: Not shown in title block; CompanyName: Not shown in title block; Engineer: Not shown in title block; Organization: Not shown in title block; Address1: Not shown in title block; Address2: Not shown in title block; Address3: Not shown in title block; Address4: Not shown in title block; DocumentNumber: 1; Revision: Use project parameter SCH_Rev; SheetNumber: 2; SheetTotal: 3; PageSetup: Record=PageOptions¦CenterHorizontal=True¦CenterVertical=True¦PrintScale=1.00¦XCorrection=1.00¦YCorrection=1.00¦PrintKind=0¦BorderSize=5000000¦LeftOffset=0¦BottomOffset=0¦Orientation=2¦PaperLength=1000¦PaperWidth=1000¦Scale=100¦PaperSource=15¦PrintQuality=600¦MediaType=1¦DitherType=10¦PaperKind=Letter¦PrintScaleMode=1
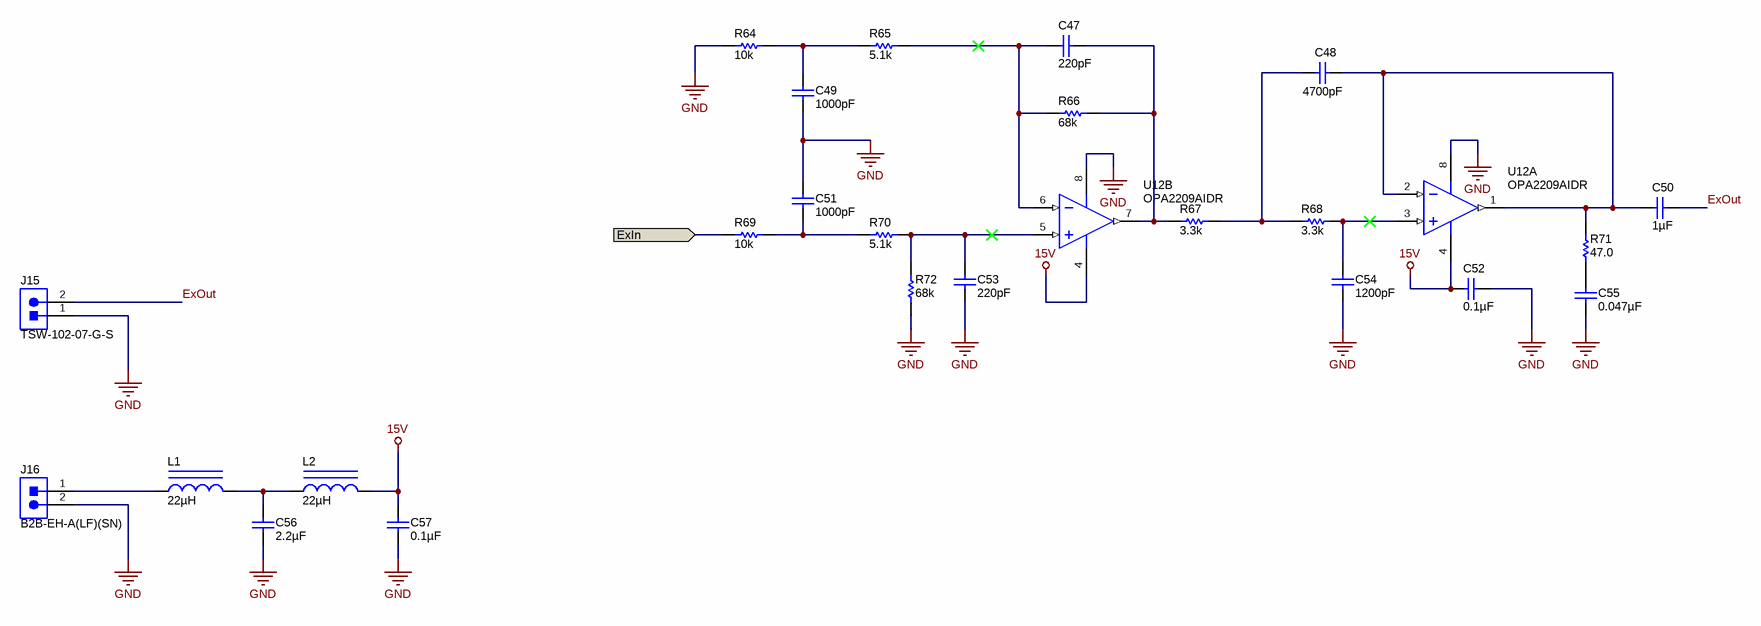
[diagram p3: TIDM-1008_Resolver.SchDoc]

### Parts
C47  ValueDisplayed: 220pF  [0603]  (hidden comment: GRM188R71H221KA01D)
C48  ValueDisplayed: 4700pF  [0603]  (hidden comment: GCM188R71H472KA37D)
C49  ValueDisplayed: 1000pF  [0603]  (hidden comment: GRM1885C1E102JA01D)
C50  ValueDisplayed: 1µF  [0805_HV]  (hidden comment: TMK212BJ105KG-T)
C51  ValueDisplayed: 1000pF  [0603]  (hidden comment: GRM1885C1E102JA01D)
C52  ValueDisplayed: 0.1µF  [0603]  (hidden comment: GRM188R71C104KA01D)
C53  ValueDisplayed: 220pF  [0603]  (hidden comment: GRM188R71H221KA01D)
C54  ValueDisplayed: 1200pF  [0603]  (hidden comment: GRM1885C1H122JA01D)
C55  ValueDisplayed: 0.047µF  [0805_HV]  (hidden comment: GRM21BR72A473KA01L)
C56  ValueDisplayed: 2.2µF  [0805_HV]  (hidden comment: TMK212BJ225KG-T)
C57  ValueDisplayed: 0.1µF  [0603]  (hidden comment: GRM188R71C104KA01D)
J15  TSW-102-07-G-S  [TSW-102-07-G-S]
J16  B2B-EH-A(LF)(SN)  [JST_B2B-EH-A]
L1  ValueDisplayed: 22µH  [0805_HV]  (hidden comment: LQM21FN220N00L)
L2  ValueDisplayed: 22µH  [0805_HV]  (hidden comment: LQM21FN220N00L)
R64  ValueDisplayed: 10k  [0603]  (hidden comment: CRCW060310K0JNEA)
R65  ValueDisplayed: 5.1k  [0603]  (hidden comment: CRCW06035K10JNEA)
R66  ValueDisplayed: 68k  [0603]  (hidden comment: CRCW060368K0JNEA)
R67  ValueDisplayed: 3.3k  [0603]  (hidden comment: CRCW06033K30JNEA)
R68  ValueDisplayed: 3.3k  [0603]  (hidden comment: CRCW06033K30JNEA)
R69  ValueDisplayed: 10k  [0603]  (hidden comment: CRCW060310K0JNEA)
R70  ValueDisplayed: 5.1k  [0603]  (hidden comment: CRCW06035K10JNEA)
R71  ValueDisplayed: 47.0  [0603]  (hidden comment: RT0603DRE0747RL)
R72  ValueDisplayed: 68k  [0603]  (hidden comment: CRCW060368K0JNEA)
U12  OPA2209AIDR  [D0008A_N]  (parts A,B of 2)

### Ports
ExIn

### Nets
15V: C52.1 C57.1 L2.2 U12.4(V-)
GND: C49.2 C51.1 C52.2 C53.2 C54.1 C55.2 C56.1 C57.2 J15.1 J16.2 R64.1 R72.1 U12.8(V+)
ExIn: R69.1 ; port ExIn
ExOut: C50.1 J15.2
NetC47_1: C47.1 R66.2 R67.1 U12.7(OUT_B)
NetC47_2: C47.2 R65.2 R66.1 U12.6(IN_B-)
NetC48_1: C48.1 C50.2 R71.2 U12.1(OUT_A) U12.2(IN_A-)
NetC48_2: C48.2 R67.2 R68.1
NetC49_1: C49.1 R64.2 R65.1
NetC51_2: C51.2 R69.2 R70.1
NetC53_1: C53.1 R70.2 R72.2 U12.5(IN_B+)
NetC54_2: C54.2 R68.2 U12.3(IN_A+)
NetC55_1: C55.1 R71.1
NetC56_2: C56.2 L1.2 L2.1
NetJ16_1: J16.1 L1.1

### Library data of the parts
C47 C53 = GRM188R71H221KA01D: as C3 on sheet TIDM-1008_SinCos
C48 = GCM188R71H472KA37D: CAP, CERM, 4700 pF, 50 V, +/- 10%, X7R, AEC-Q200 Grade 1, 0603; Manufacturer: MuRata; Polarized: N; CompType: Capacitor; Value: 4700pF; U/M: EA; Cap_F: 0.0000000047; Tolerance_%: 10; Value1: Unknown; VDC_V: 50; Value2: 50V; TaMin_C: -55; TaMax_C: 125; SizeArea_mm2: 1.28; SizeAreaWB_mm2: 4.68; SizeX_mm: 1.6; SizeY_mm: 0.8; SizeZ_mm: 1; AEC Category: Q200; AEC Qualified: Y
C49 C51 = GRM1885C1E102JA01D: CAP, CERM, 1000 pF, 25 V, +/- 5%, C0G/NP0, 0603; Manufacturer: MuRata; Polarized: N; CompType: Capacitor; Value: 1000pF; U/M: EA; Cap_F: 0.000000001; Tolerance_%: 5; Value1: Unknown; VDC_V: 25; Value2: 25V; TaMin_C: -55; TaMax_C: 125; SizeArea_mm2: 1.28; SizeAreaWB_mm2: 4.68; SizeX_mm: 1.6; SizeY_mm: 0.8; SizeZ_mm: 1; AEC Category: Q200
C50 = TMK212BJ105KG-T: CAP, CERM, 1 µF, 20 V, +/- 10%, X5R, 0805; Manufacturer: Taiyo Yuden; Polarized: N; CompType: Capacitor; Value: 1uF; U/M: EA; Cap_F: 0.000001; Tolerance_%: 10; Value1: Unknown; VDC_V: 20; Value2: 20V; TaMin_C: -55; TaMax_C: 85; Cap_Case: 0805; SizeArea_mm2: 2.5; SizeAreaWB_mm2: 6.75; SizeX_mm: 2; SizeY_mm: 1.25; SizeZ_mm: 1.45; AEC Category: Q200
C52 C57 = GRM188R71C104KA01D: CAP, CERM, 0.1 µF, 16 V, +/- 10%, X7R, 0603; Manufacturer: MuRata; Polarized: N; CompType: Capacitor; Value: 0.1uF; U/M: EA; Cap_F: 0.0000001; Tolerance_%: 10; Value1: Unknown; VDC_V: 16; Value2: 16V; TaMin_C: -55; TaMax_C: 125; SizeArea_mm2: 1.28; SizeAreaWB_mm2: 4.68; SizeX_mm: 1.6; SizeY_mm: 0.8; SizeZ_mm: 1; AEC Category: Q200
C54 = GRM1885C1H122JA01D: CAP, CERM, 1200 pF, 50 V, +/- 5%, C0G/NP0, 0603; Manufacturer: MuRata; Polarized: N; CompType: Capacitor; Value: 1200pF; U/M: EA; Cap_F: 0.0000000012; Tolerance_%: 5; Value1: Unknown; VDC_V: 50; Value2: 50V; TaMin_C: -55; TaMax_C: 125; SizeArea_mm2: 1.28; SizeAreaWB_mm2: 4.68; SizeX_mm: 1.6; SizeY_mm: 0.8; SizeZ_mm: 1; AEC Category: Q200
C55 = GRM21BR72A473KA01L: CAP, CERM, 0.047 µF, 100 V, +/- 10%, X7R, 0805; Manufacturer: MuRata; Polarized: N; CompType: Capacitor; Value: 0.047uF; U/M: EA; Cap_F: 0.000000047; Tolerance_%: 10; Value1: Unknown; VDC_V: 100; Value2: 100V; TaMin_C: -55; TaMax_C: 125; Cap_Case: 0805; SizeArea_mm2: 2.5; SizeAreaWB_mm2: 6.75; SizeX_mm: 2; SizeY_mm: 1.25; SizeZ_mm: 1.45; AEC Category: Q200
C56 = TMK212BJ225KG-T: CAP, CERM, 2.2 µF, 20 V, +/- 10%, X5R, 0805; Manufacturer: Taiyo Yuden; Polarized: N; CompType: Capacitor; Value: 2.2uF; U/M: EA; Cap_F: 0.0000022; Tolerance_%: 10; Value1: Unknown; VDC_V: 20; Value2: 20V; TaMin_C: -55; TaMax_C: 85; Cap_Case: 0805; SizeArea_mm2: 2.5; SizeAreaWB_mm2: 6.75; SizeX_mm: 2; SizeY_mm: 1.25; SizeZ_mm: 1.45; AEC Category: Q200
J15 = TSW-102-07-G-S: Header, 100mil, 2x1, Gold, TH; Manufacturer: Samtec; SymbolCreator: a0412235; Pitch_mm: 2.54; Gender: Male; Shrouded: N; Row_Count: 1; Current_A: 6.3; Voltage_V: 550; Cert_CSA: Y
J16 = B2B-EH-A(LF)(SN): Header (Shrouded), 2.5mm, 2x1, Tin, TH; Manufacturer: JST Manufacturing; SymbolCreator: a0412235; Pitch_mm: 2.5; Gender: Male; Shrouded: Y; Row_Count: 1; Current_A: 3; Voltage_V: 250
L1 L2 = LQM21FN220N00L: Inductor, Shielded, Ferrite, 22 µH, 0.013 A, 0.455 ohm, SMD; Manufacturer: MuRata; Value: 22uH; Ind_H: 22.0E-6; Imax_A: 0.013; Irms: 0.013A @ C rise; DCR_ohm: 0.455; Value2: 0.013A; AEC Category: Q200; AEC Qualified: N
R64 R69 = CRCW060310K0JNEA: RES, 10 k, 5%, 0.1 W, 0603; Manufacturer: Vishay-Dale; CompType: Resistor; Value: 10k; Res_ohm: 10000; Value_Code: 10k0; Tolerance_%: 5; Power_W: 0.1; Value2: 0.1W; VDC_V: 75; TempCo: 200 ppm/C; SizeArea_mm2: 1.28; SizeX_mm: 1.6; SizeY_mm: 0.8; SizeZ_mm: 1; EIA_Code: E24; U/M: EA; AEC Category: Q200
R65 R70 = CRCW06035K10JNEA: RES, 5.1 k, 5%, 0.1 W, 0603; Manufacturer: Vishay-Dale; CompType: Resistor; Value: 5.1k; Res_ohm: 5100; Value_Code: 5k10; Tolerance_%: 5; Power_W: 0.1; Value2: 0.1W; VDC_V: 75; TempCo: 200 ppm/C; SizeArea_mm2: 1.28; SizeX_mm: 1.6; SizeY_mm: 0.8; SizeZ_mm: 1; EIA_Code: E24; U/M: EA; AEC Category: Q200
R66 R72 = CRCW060368K0JNEA: RES, 68 k, 5%, 0.1 W, 0603; Manufacturer: Vishay-Dale; CompType: Resistor; Value: 68k; Res_ohm: 68000; Value_Code: 68k0; Tolerance_%: 5; Power_W: 0.1; Value2: 0.1W; VDC_V: 75; TempCo: 200 ppm/C; SizeArea_mm2: 1.28; SizeX_mm: 1.6; SizeY_mm: 0.8; SizeZ_mm: 1; EIA_Code: E24; U/M: EA; AEC Category: Q200
R67 R68 = CRCW06033K30JNEA: RES, 3.3 k, 5%, 0.1 W, 0603; Manufacturer: Vishay-Dale; CompType: Resistor; Value: 3.3k; Res_ohm: 3300; Value_Code: 3k30; Tolerance_%: 5; Power_W: 0.1; Value2: 0.1W; VDC_V: 75; TempCo: 200 ppm/C; SizeArea_mm2: 1.28; SizeX_mm: 1.6; SizeY_mm: 0.8; SizeZ_mm: 1; EIA_Code: E24; U/M: EA; AEC Category: Q200
R71 = RT0603DRE0747RL: RES, 47.0, 0.5%, 0.1 W, 0603; Manufacturer: Yageo America; CompType: Resistor; Value: 47.0; Res_ohm: 47; Value_Code: 47R0; Tolerance_%: 0.5; Power_W: 0.1; Value2: 0.1W; VDC_V: 75; TempCo: 50 ppm/C; SizeArea_mm2: 1.28; SizeX_mm: 1.6; SizeY_mm: 0.8; SizeZ_mm: 1; EIA_Code: E192; U/M: EA; AEC Category: Q200
U12 = OPA2209AIDR: 2.2 nV/rtHz, 18 MHz, Precision, RRO, Operational Amplifier, 4.5 to 36 V, -40 to 125 degC, 8-pin SOIC (D0008A), Green (RoHS & no Sb/Br); Manufacturer: Texas Instruments; Alternate PartNumber: Equivalent; CMRR(Min)(dB): 120; GBW(Typ)(MHz): 18; IIB(Max)(pA): 4500; Iq per channel(Max)(mA): 2.5; Number of Channels: 2; Offset Drift(Typ)(uV/C): 1; Packing: LARGE T&R; Rating: Catalog; Slew Rate(Typ)(V/us): 6.4; Sub Family: High Supply Voltage Amplifier (>=30V), Low Noise Amp (<=10nV/rtHz), Low Offset Voltage Amplifier (<=500uV), Precision Amplifier; Total Supply Voltage(Max)(+5V is 5, +/-5V is 10): 36; Total Supply Voltage(Min)(+5V is 5, +/-5V is 10): 4.5; Vio (25C)(Max)(mV): 0.15

## Sheet TIDM-1008_PowerAndInterface.SchDoc
size 431 x 279 mm; Date: Not shown in title block; ApprovedBy: Not shown in title block; CheckedBy: Not shown in title block; Author: Not shown in title block; CompanyName: Not shown in title block; Engineer: Not shown in title block; Organization: Not shown in title block; Address1: Not shown in title block; Address2: Not shown in title block; Address3: Not shown in title block; Address4: Not shown in title block; DocumentNumber: 1; Revision: Use project parameter SCH_Rev; SheetNumber: 2; SheetTotal: 3; PageSetup: Record=PageOptions¦CenterHorizontal=True¦CenterVertical=True¦PrintScale=0.62¦XCorrection=1.00¦YCorrection=1.00¦PrintKind=0¦BorderSize=5000000¦LeftOffset=0¦BottomOffset=0¦Orientation=2¦PaperLength=1000¦PaperWidth=1000¦Scale=100¦PaperSource=15¦PrintQuality=600¦MediaType=1¦DitherType=10¦PrintScaleMode=1¦PaperKind=Letter
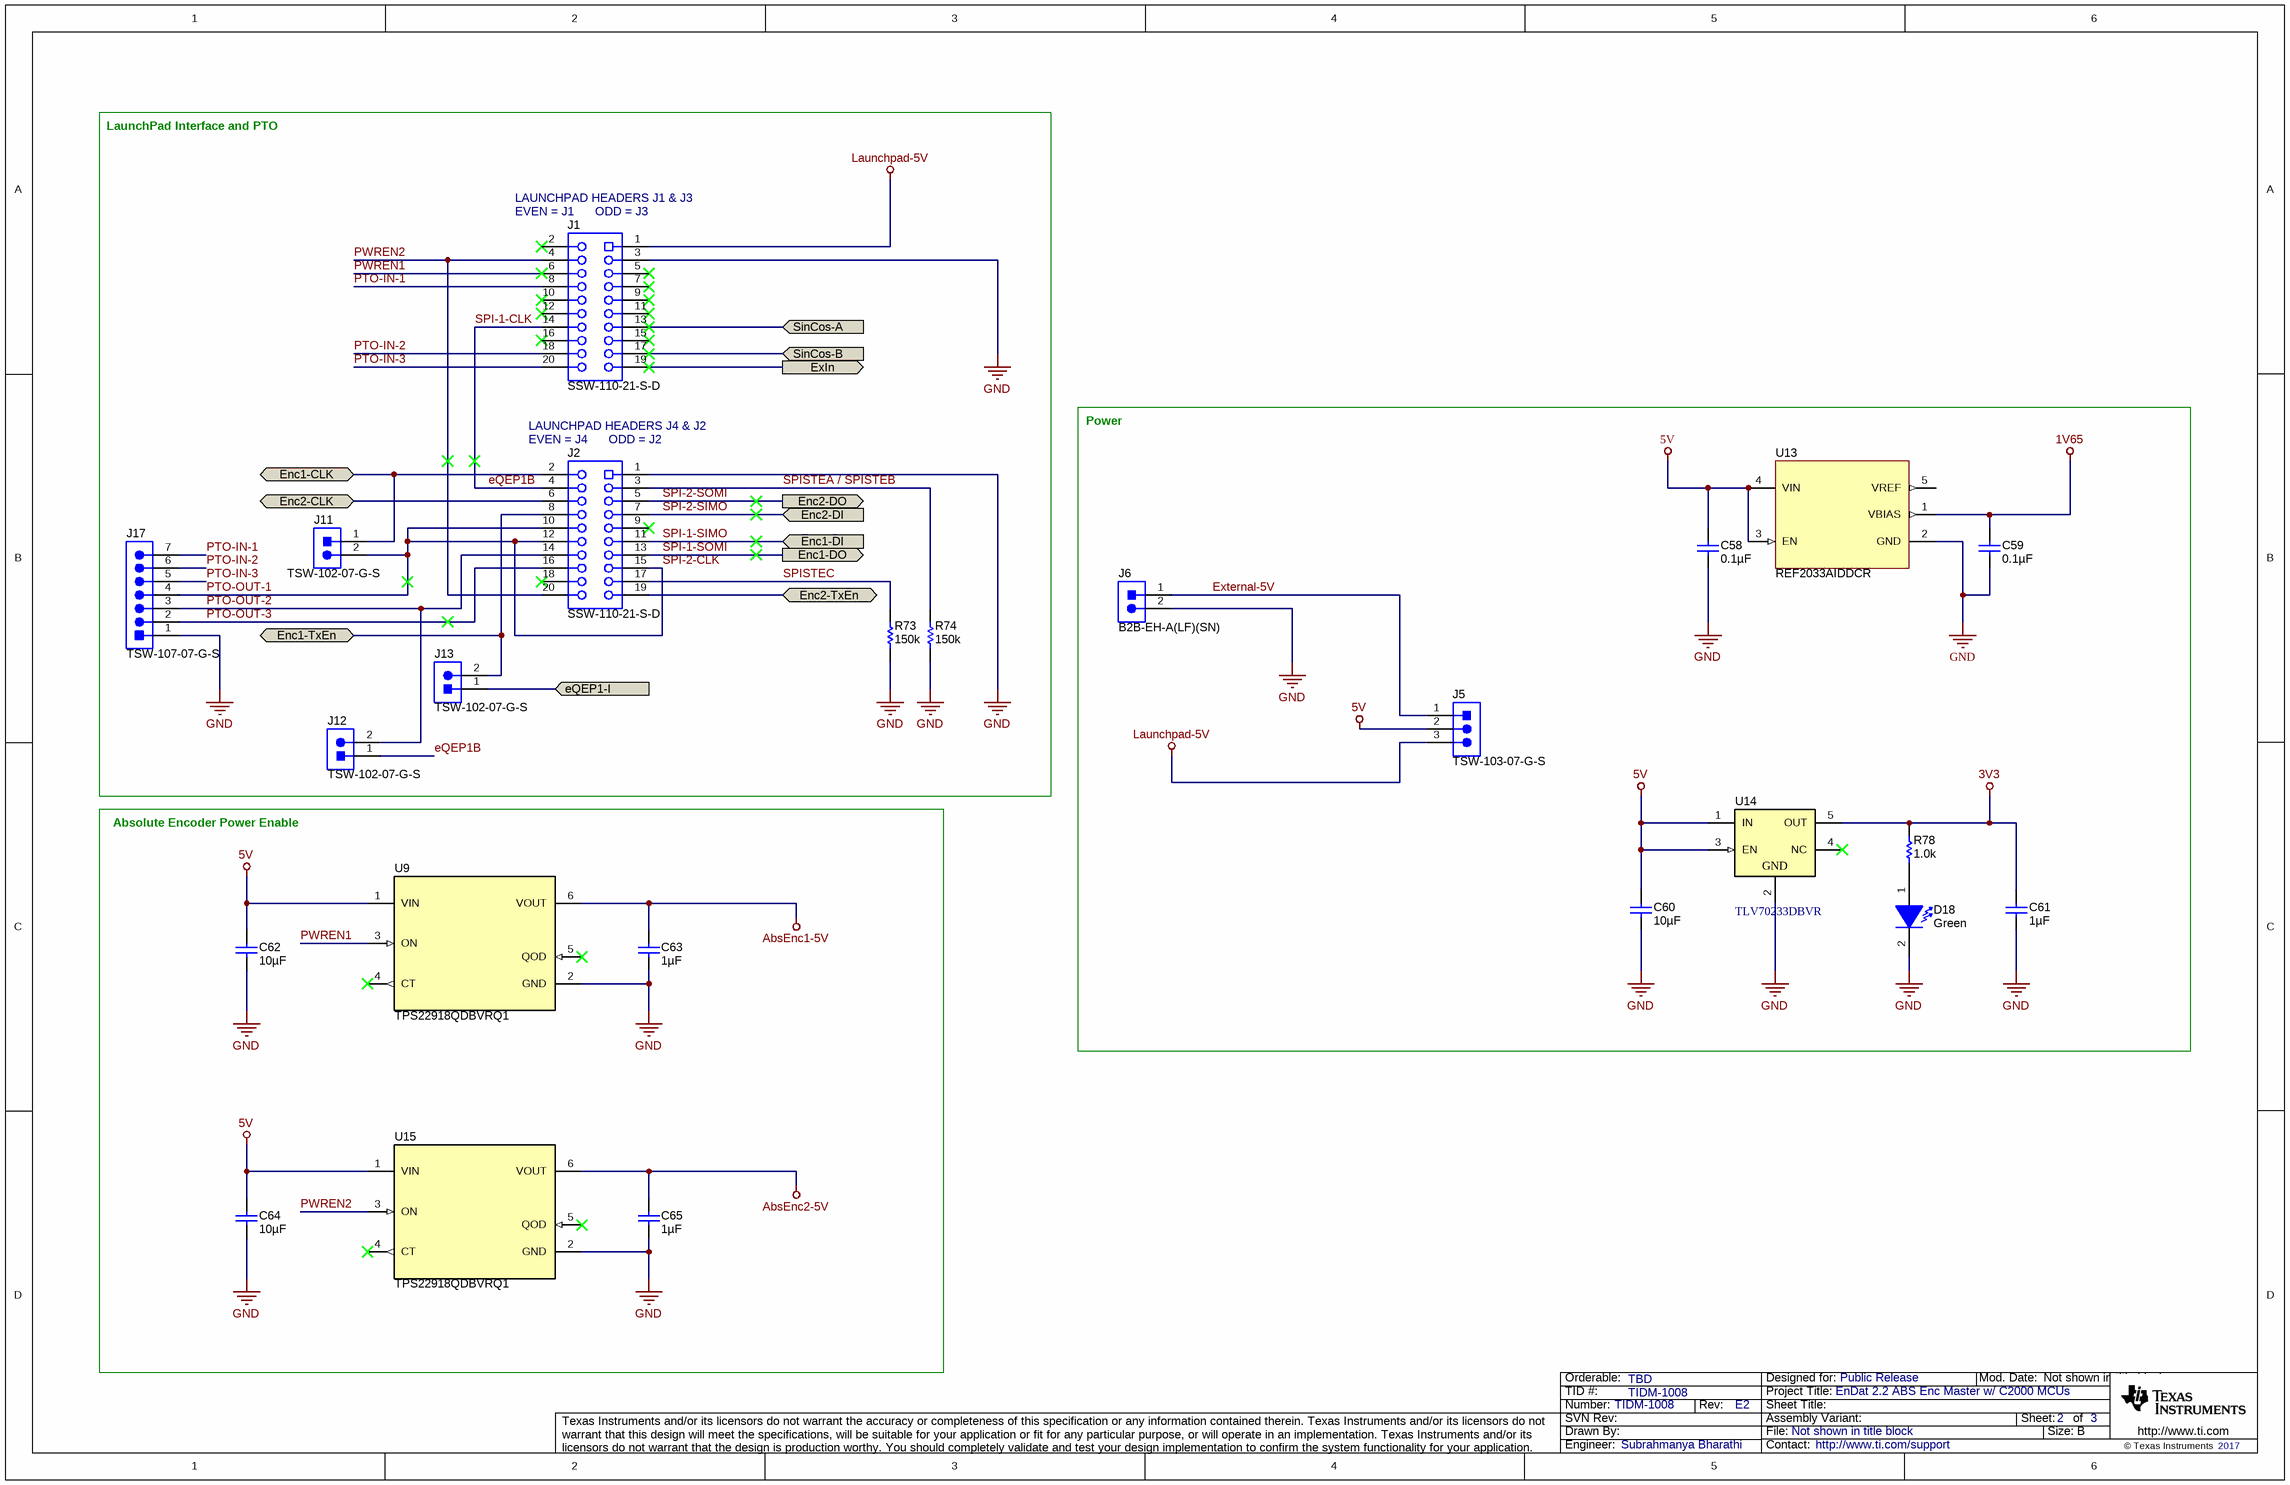
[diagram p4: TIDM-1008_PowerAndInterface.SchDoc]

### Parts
C58  ValueDisplayed: 0.1µF  [0603]  (hidden comment: GRM188R71C104KA01D)
C59  ValueDisplayed: 0.1µF  [0603]  (hidden comment: GRM188R71C104KA01D)
C60  ValueDisplayed: 10µF  [0805_HV]  (hidden comment: GRM21BR61E106KA73L)
C61  ValueDisplayed: 1µF  [0805_HV]  (hidden comment: TMK212BJ105KG-T)
C62  ValueDisplayed: 10µF  [0805_HV]  (hidden comment: GRM21BR61E106KA73L)
C63  ValueDisplayed: 1µF  [0805_HV]  (hidden comment: TMK212BJ105KG-T)
C64  ValueDisplayed: 10µF  [0805_HV]  (hidden comment: GRM21BR61E106KA73L)
C65  ValueDisplayed: 1µF  [0805_HV]  (hidden comment: TMK212BJ105KG-T)
D18  value Green  [LG L29K_GREEN]  (hidden comment: LG L29K-G2J1-24-Z)
J1  SSW-110-21-S-D  [Samtec_SSW-110-x1-x-D]
J2  SSW-110-21-S-D  [Samtec_SSW-110-x1-x-D]
J5  TSW-103-07-G-S  [TSW-103-07-G-S]
J6  B2B-EH-A(LF)(SN)  [JST_B2B-EH-A]
J11  TSW-102-07-G-S  [TSW-102-07-G-S]
J12  TSW-102-07-G-S  [TSW-102-07-G-S]
J13  TSW-102-07-G-S  [TSW-102-07-G-S]
J17  TSW-107-07-G-S  [TSW-107-07-G-S]
R73  ValueDisplayed: 150k  [0603]  (hidden comment: CRCW0603150KFKEA)
R74  ValueDisplayed: 150k  [0603]  (hidden comment: CRCW0603150KFKEA)
R78  ValueDisplayed: 1.0k  [0402]  (hidden comment: CRCW04021K00JNED)
U9  TPS22918QDBVRQ1  [DBV0006A_N]
U13  REF2033AIDDCR  [DDC0005A_N]
U14  TLV70233DBVR  [DBV0005A_N]
U15  TPS22918QDBVRQ1  [DBV0006A_N]

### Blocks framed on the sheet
Power: C58-C61 D18 J5 J6 R78 U13 U14
Absolute Encoder Power Enable: C62-C65 U9 U15

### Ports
Enc1-CLK (bidir), Enc1-DI (in), Enc1-DO (out), Enc1-TxEn (bidir), Enc2-CLK (bidir), Enc2-DI (in), Enc2-DO (out), Enc2-TxEn (bidir), eQEP1-I (in), ExIn (out), SinCos-A (in), SinCos-B (in)

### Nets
1V65: C59.2 U13.1(VBIAS)
3V3: C61.1 R78.2 U14.5(OUT)
5V: C58.2 C60.1 C62.1 C64.1 J5.2 U9.1(VIN) U13.3(EN) U13.4(VIN) U14.1(IN) U14.3(EN) U15.1(VIN)
AbsEnc1-5V: C63.1 U9.6(VOUT)
AbsEnc2-5V: C65.1 U15.6(VOUT)
GND: C58.1 C59.1 C60.2 C61.2 C62.2 C63.2 C64.2 C65.2 D18.2(K) J1.3 J2.1 J6.2 J17.1 R73.1 R74.1 U9.2(GND) U13.2(GND) U14.2(GND) U15.2(GND)
Launchpad-5V: J1.1 J5.3
Enc1-CLK: J2.2 J11.1 ; port Enc1-CLK
Enc1-TxEn: J2.8 J13.2 ; port Enc1-TxEn
Enc2-CLK: J2.6 ; port Enc2-CLK
Enc2-TxEn: J2.19 ; port Enc2-TxEn
eQEP1-I: J13.1 ; port eQEP1-I
eQEP1B: J1.14 J2.4 J12.1  [also labelled SPI-1-CLK]
ExIn: J1.19 ; port ExIn
External-5V: J5.1 J6.1
PTO-IN-1: J1.8 J17.7
PTO-IN-2: J1.18 J17.6
PTO-IN-3: J1.20 J17.5
PTO-OUT-1: J2.10 J2.12 J2.15 J11.2 J17.4  [also labelled SPI-2-CLK]
PTO-OUT-2: J2.14 J12.2 J17.3
PTO-OUT-3: J2.16 J17.2
PWREN1: J1.6 U9.3(ON)
PWREN2: J1.4 J2.20 U15.3(ON)
SinCos-A: J1.13 ; port SinCos-A
SinCos-B: J1.17 ; port SinCos-B
SPI-1-SIMO: J2.11 ; port Enc1-DI
SPI-1-SOMI: J2.13 ; port Enc1-DO
SPI-2-SIMO: J2.7 ; port Enc2-DI
SPI-2-SOMI: J2.5 ; port Enc2-DO
SPISTEA / SPISTEB: J2.3 R74.2
SPISTEC: J2.17 R73.2
NetD18_1: D18.1(A) R78.1

Not connected (* = marked no-connect by the designer): J1 2* 5* 7* 9* 10* 11* 12* 15* 16*; J2 9* 18*; U9 4(CT)* 5(QOD)*; U13 5(VREF); U14 4(NC)*; U15 4(CT)* 5(QOD)*

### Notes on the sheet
- LaunchPad Interface and PTO
- (near J1) LAUNCHPAD HEADERS J1 & J3
- (near J1) EVEN = J1      ODD = J3
- LAUNCHPAD HEADERS J4 & J2
- (near J2) EVEN = J4      ODD = J2

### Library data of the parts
C58 C59 = GRM188R71C104KA01D: as C2 on sheet TIDM-1008_SinCos
C60 C62 C64 = GRM21BR61E106KA73L: CAP, CERM, 10 µF, 25 V,+/- 10%, X5R, 0805; Manufacturer: MuRata; Polarized: N; CompType: Capacitor; Value: 10uF; U/M: EA; Cap_F: 0.00001; Tolerance_%: 10; Value1: Unknown; VDC_V: 25; Value2: 25V; TaMin_C: -55; TaMax_C: 85; Cap_Case: 0805; SizeArea_mm2: 2.5; SizeAreaWB_mm2: 6.75; SizeX_mm: 2; SizeY_mm: 1.25; SizeZ_mm: 1.45; AEC Category: Q200; Green_Lifecycle: Active; Green_REACh: Passed
C61 C63 C65 = TMK212BJ105KG-T: as C50 on sheet TIDM-1008_Resolver
D18 = LG L29K-G2J1-24-Z: LED, Green, SMD; Manufacturer: OSRAM; Vf_V: 1.7; Value2: 1.7V; Io_A: 0.002; Tjmax_C: 110; Value1: W; U/M: EA
J1 J2 = SSW-110-21-S-D: Receptacle, 2.54mm, 10x2, Gold, TH; Manufacturer: Samtec; SymbolCreator: a0412235; Pitch_mm: 2.54; Gender: Female; Row_Count: 2
J5 = TSW-103-07-G-S: as J9 on sheet TIDM-1008_AbsEnc
J6 = B2B-EH-A(LF)(SN): as J16 on sheet TIDM-1008_Resolver
J11-J13 = TSW-102-07-G-S: as J15 on sheet TIDM-1008_Resolver
J17 = TSW-107-07-G-S: Header, 100mil, 7x1, Gold, TH; Manufacturer: Samtec; SymbolCreator: a0411947; Pitch_mm: 2.54; Gender: Male; Shrouded: N; Row_Count: 1; Current_A: 6.3; Voltage_V: 550; Cert_CSA: Y
R73 R74 = CRCW0603150KFKEA: RES, 150 k, 1%, 0.1 W, 0603; Manufacturer: Vishay-Dale; CompType: Resistor; Value: 150k; Res_ohm: 150000; Tolerance_%: 1; Power_W: 0.1; Value2: 0.1W; VDC_V: 75; TempCo: 100 ppm/C; SizeArea_mm2: 1.28; SizeX_mm: 1.6; SizeY_mm: 0.8; EIA_Code: E96; U/M: EA; AEC Category: Q200
R78 = CRCW04021K00JNED: as R48 on sheet TIDM-1008_AbsEnc
U9 U15 = TPS22918QDBVRQ1: 5.5-V, 2-A, 54mohm On-Resistance Load Switch, DBV0006A (SOT-23-6); Manufacturer: Texas Instruments; SymbolCreator: Altium; SizeArea_mm2: 8.12; SizeAreaWB_mm2: 14.82; SizeX_mm: 2.8; SizeY_mm: 2.9; SizeZ_mm: 1.45; CompType: IC; U/M: EA
U13 = REF2033AIDDCR: Low-Drift, Low-Power, Dual-Output, VREF and VREF / 2 Voltage References, DDC0005A; Alternate PartNumber: REF2033AIDDCT; Manufacturer: Texas Instruments; SymbolCreator: a0799628; CompType: IC; U/M: EA
U14 = TLV70233DBVR: Single Output LDO, 300 mA, Fixed 3.3 V Output, 2 to 5.5 V Input, with Low IQ, 5-pin SOT-23 (DBV), -40 to 125 degC, Green (RoHS & no Sb/Br); Manufacturer: Texas Instruments; Alternate PartNumber: Equivalent; Accuracy(%): 2; Fixed Output Options(V): 3.3; Iout(Max)(A): 0.3; Iq(Typ)(mA): 0.03; SubFamily: Single Channel LDO; Vdo(Typ)(mV): 220; Vin(Max)(V): 5.5

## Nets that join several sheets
1V65: TIDM-1008_SinCos (10 pins), TIDM-1008_PowerAndInterface (C59.2 U13.1)
3V3: TIDM-1008_SinCos (D3.1 D8.1 D13.1 R21.2), TIDM-1008_AbsEnc (18 pins), TIDM-1008_PowerAndInterface (C61.1 R78.2 U14.5)
5V: TIDM-1008_SinCos (17 pins), TIDM-1008_PowerAndInterface (11 pins)
AbsEnc1-5V: TIDM-1008_AbsEnc (J7.7 R48.2), TIDM-1008_PowerAndInterface (C63.1 U9.6)
AbsEnc2-5V: TIDM-1008_AbsEnc (J8.7 R54.2), TIDM-1008_PowerAndInterface (C65.1 U15.6)
GND: TIDM-1008_SinCos (39 pins), TIDM-1008_AbsEnc (25 pins), TIDM-1008_Resolver (13 pins), TIDM-1008_PowerAndInterface (19 pins)
Enc1-CLK: TIDM-1008_AbsEnc (R46.1 U8.4), TIDM-1008_PowerAndInterface (J2.2 J11.1)
Enc1-TxEn: TIDM-1008_AbsEnc (R37.2 R40.1 U7.3), TIDM-1008_PowerAndInterface (J2.8 J13.2)
Enc2-CLK: TIDM-1008_AbsEnc (J10.1 R62.1 U11.4), TIDM-1008_PowerAndInterface (J2.6)
Enc2-TxEn: TIDM-1008_AbsEnc (J10.2 R52.2 R56.1 U10.3), TIDM-1008_PowerAndInterface (J2.19)
eQEP1-I: TIDM-1008_SinCos (R31.2 U6.1), TIDM-1008_PowerAndInterface (J13.1)
ExIn: TIDM-1008_Resolver (R69.1), TIDM-1008_PowerAndInterface (J1.19)
SinCos-A: TIDM-1008_SinCos (C7.1 R6.2), TIDM-1008_PowerAndInterface (J1.13)
SinCos-B: TIDM-1008_SinCos (C17.1 R15.2), TIDM-1008_PowerAndInterface (J1.17)
SPI-1-SIMO: TIDM-1008_AbsEnc (R36.1), TIDM-1008_PowerAndInterface (J2.11)
SPI-1-SOMI: TIDM-1008_AbsEnc (R41.2 U7.4), TIDM-1008_PowerAndInterface (J2.13)
SPI-2-SIMO: TIDM-1008_AbsEnc (J10.4 R51.1), TIDM-1008_PowerAndInterface (J2.7)
SPI-2-SOMI: TIDM-1008_AbsEnc (J10.3 R57.2 U10.4), TIDM-1008_PowerAndInterface (J2.5)

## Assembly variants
001: not fitted FID1 FID2 FID3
